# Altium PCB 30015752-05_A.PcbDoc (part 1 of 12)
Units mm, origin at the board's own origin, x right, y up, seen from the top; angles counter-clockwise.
Board outline 100.05 x 72 mm, 10 copper layers (Top, GND_2, Signal_3, Signal_4, PWR_5, GND_6, Signal_7, Signal_8, GND_9, Bottom), stack 1.493 mm thick; 577 components, 546 nets, 2389 pads, 1412 vias.
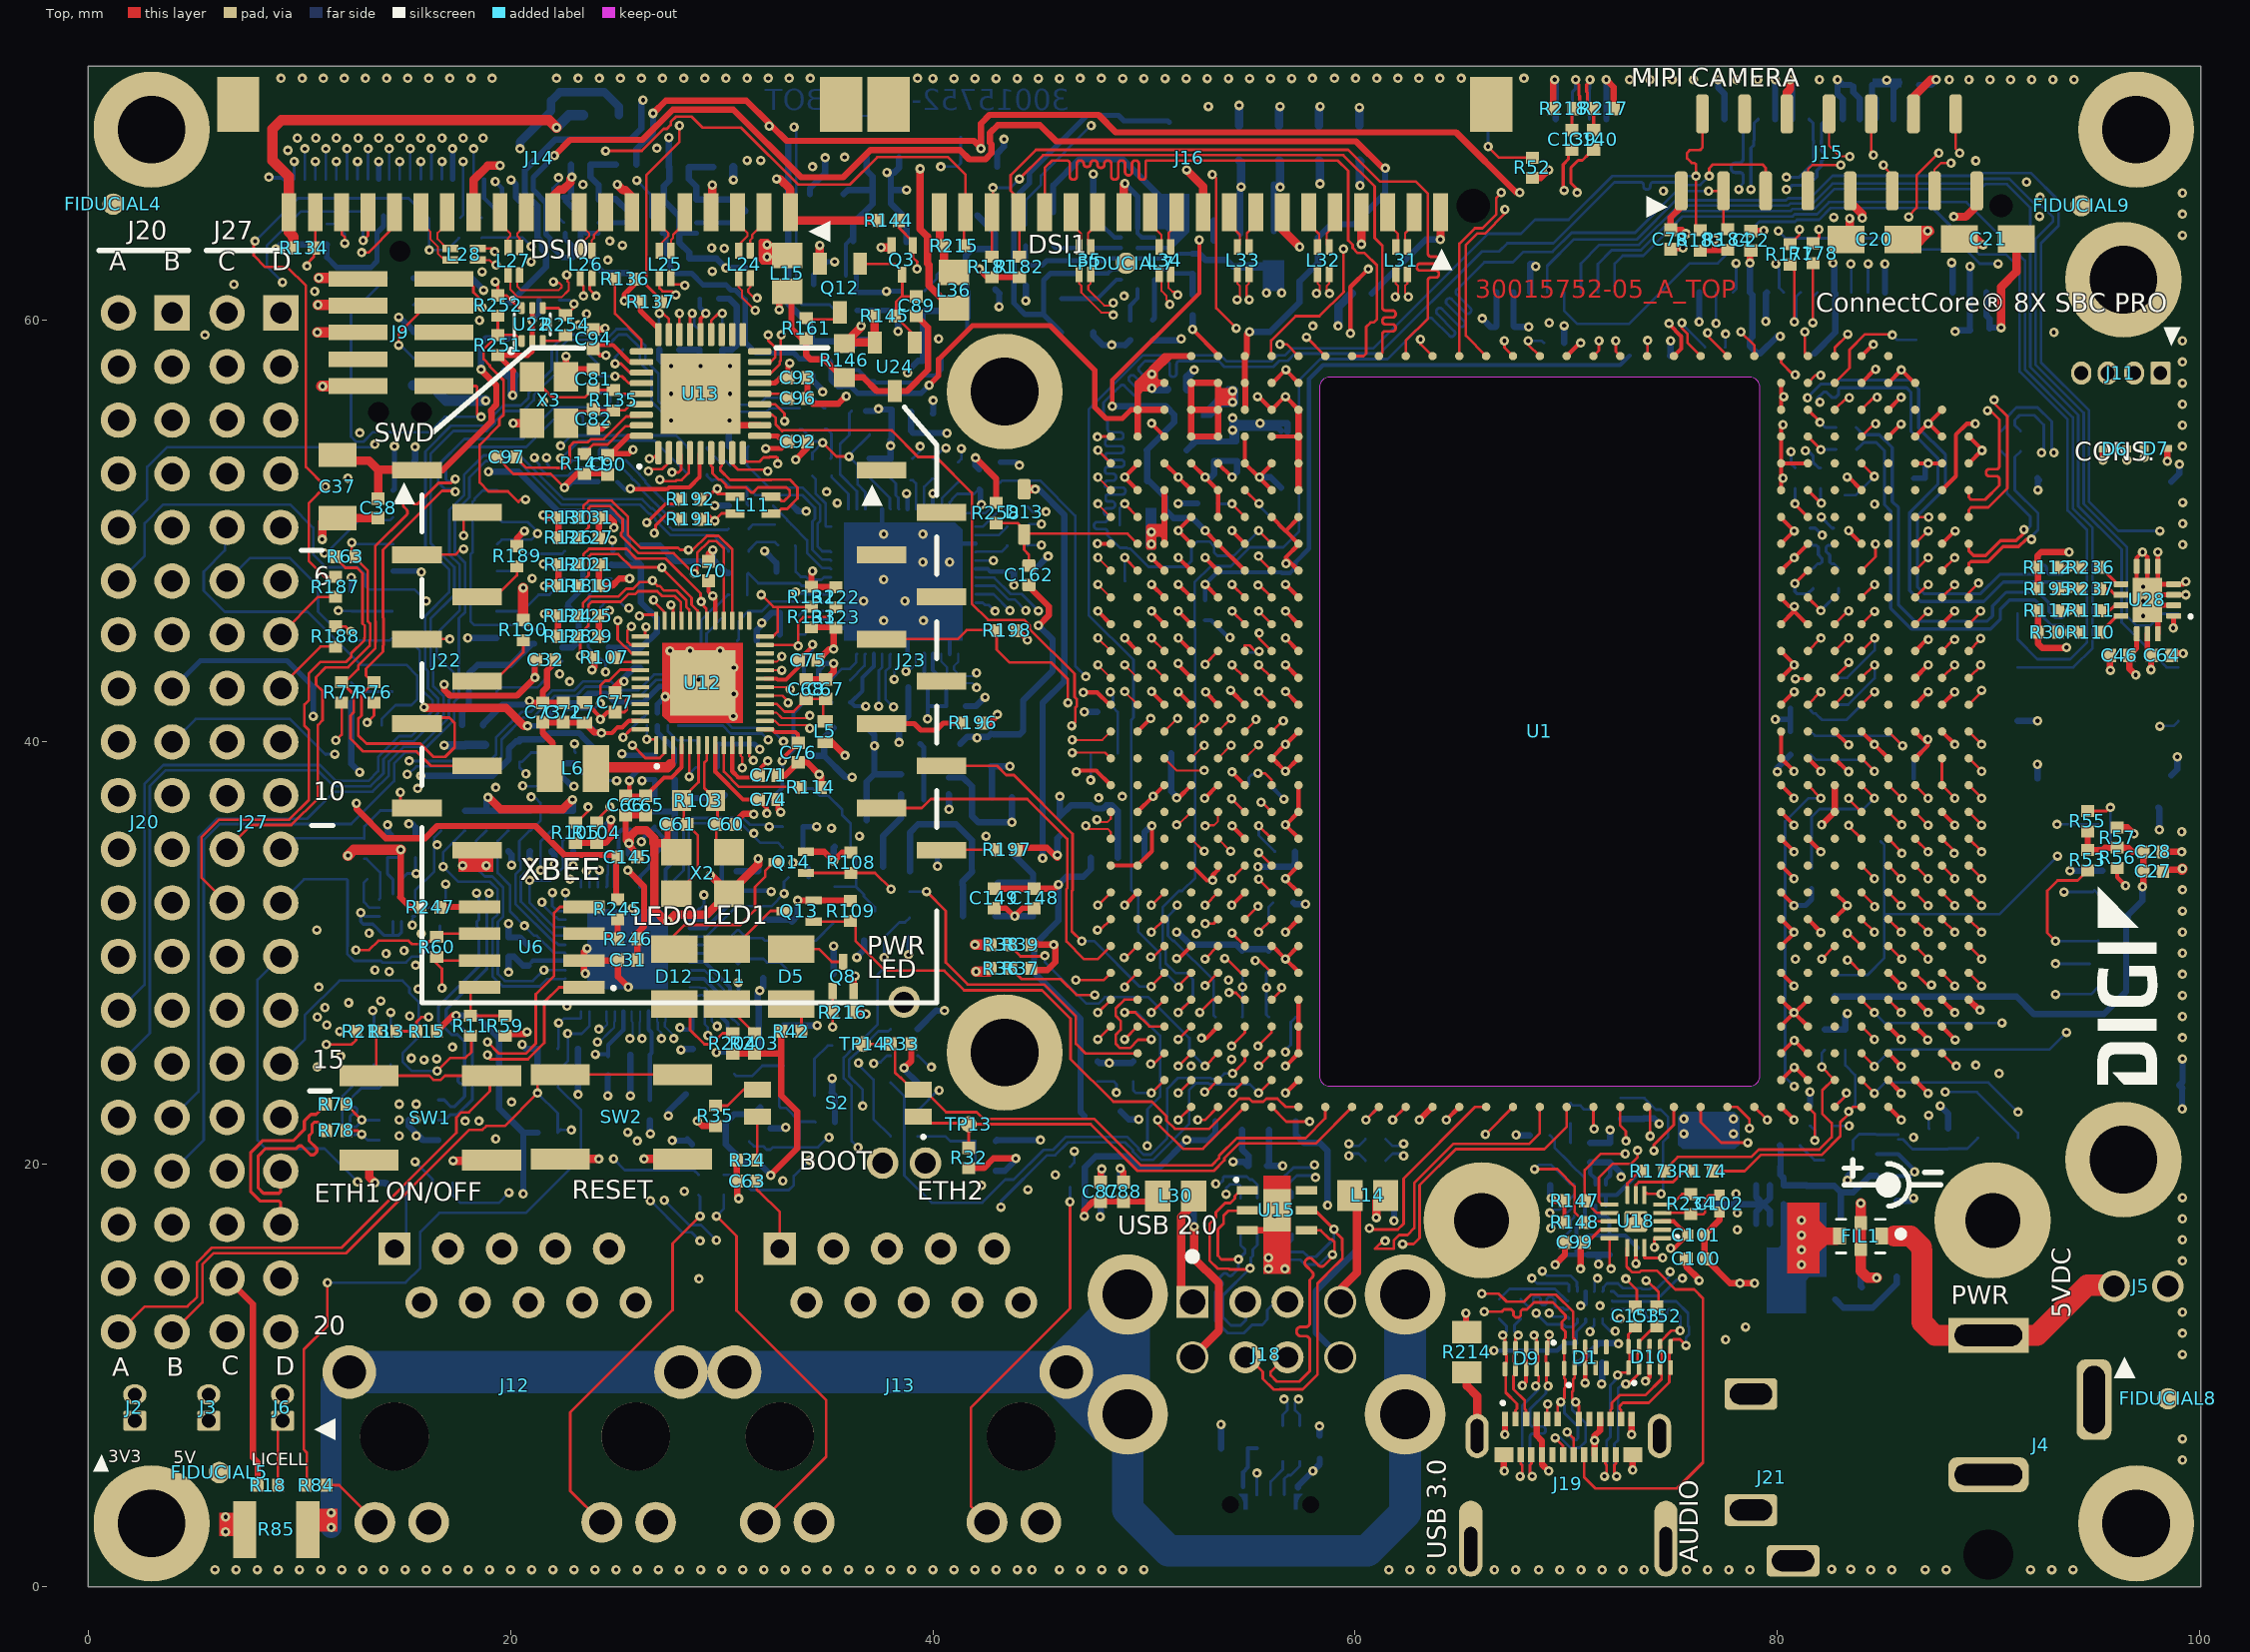
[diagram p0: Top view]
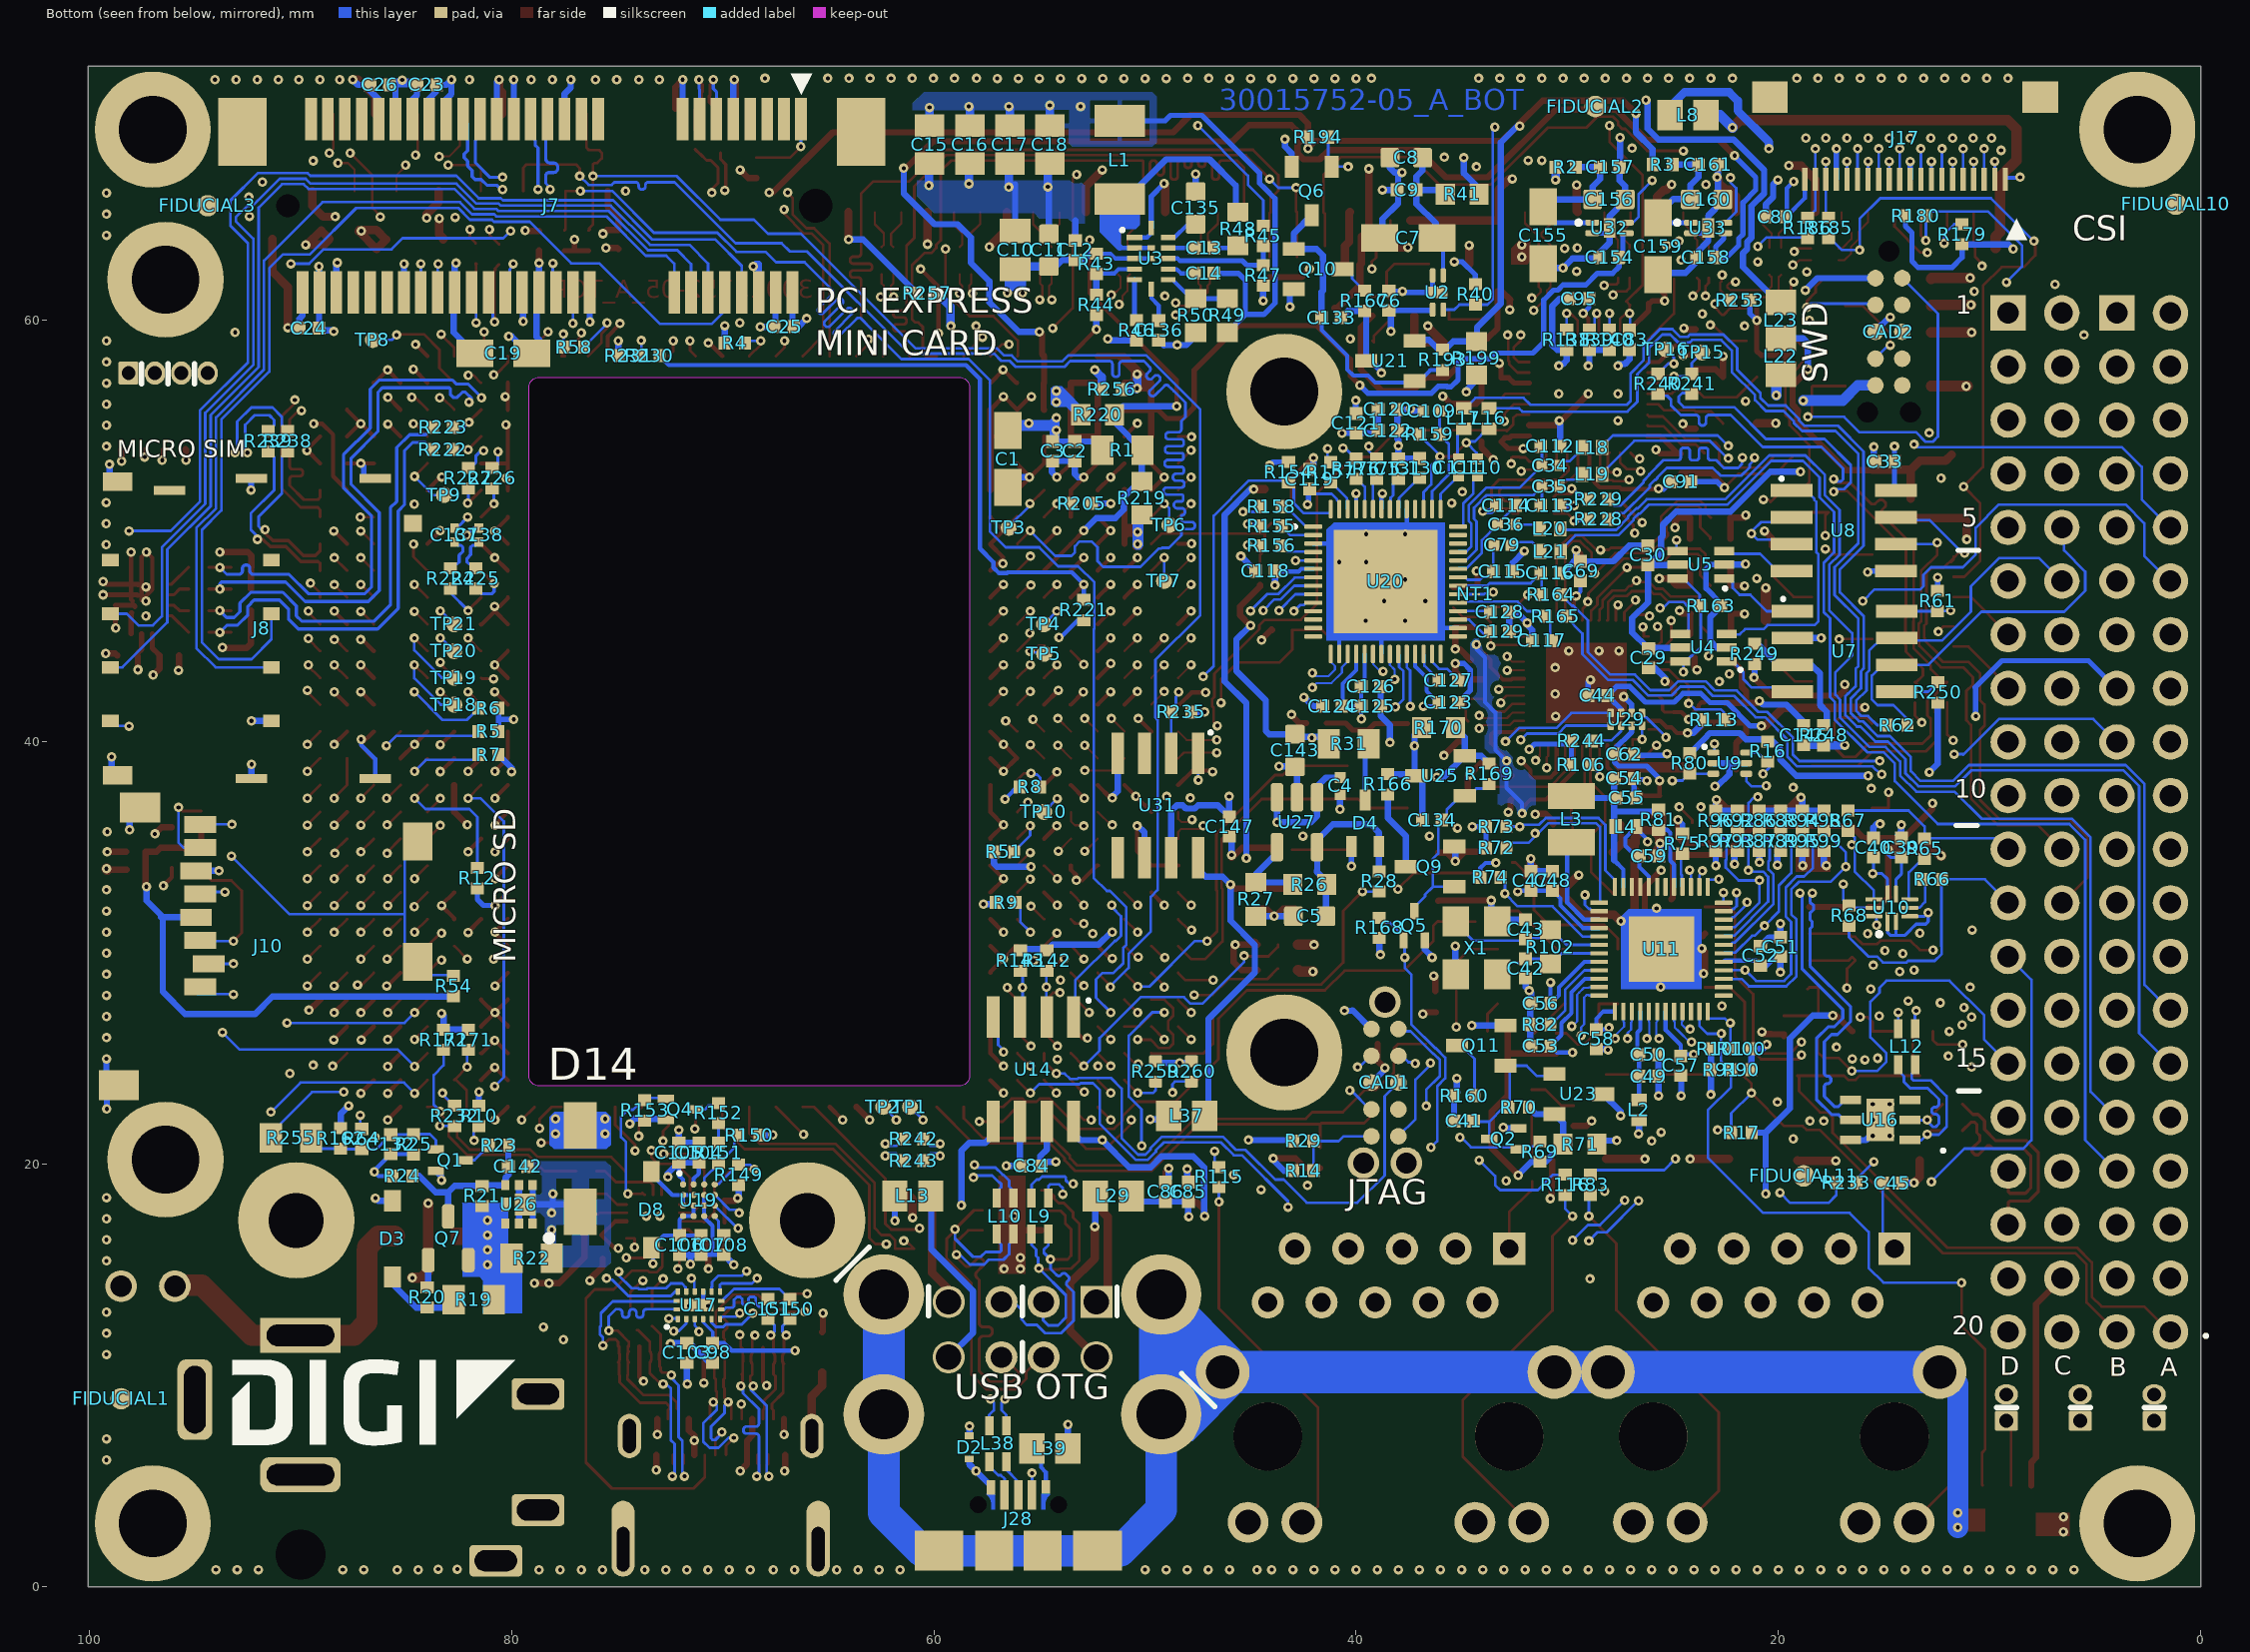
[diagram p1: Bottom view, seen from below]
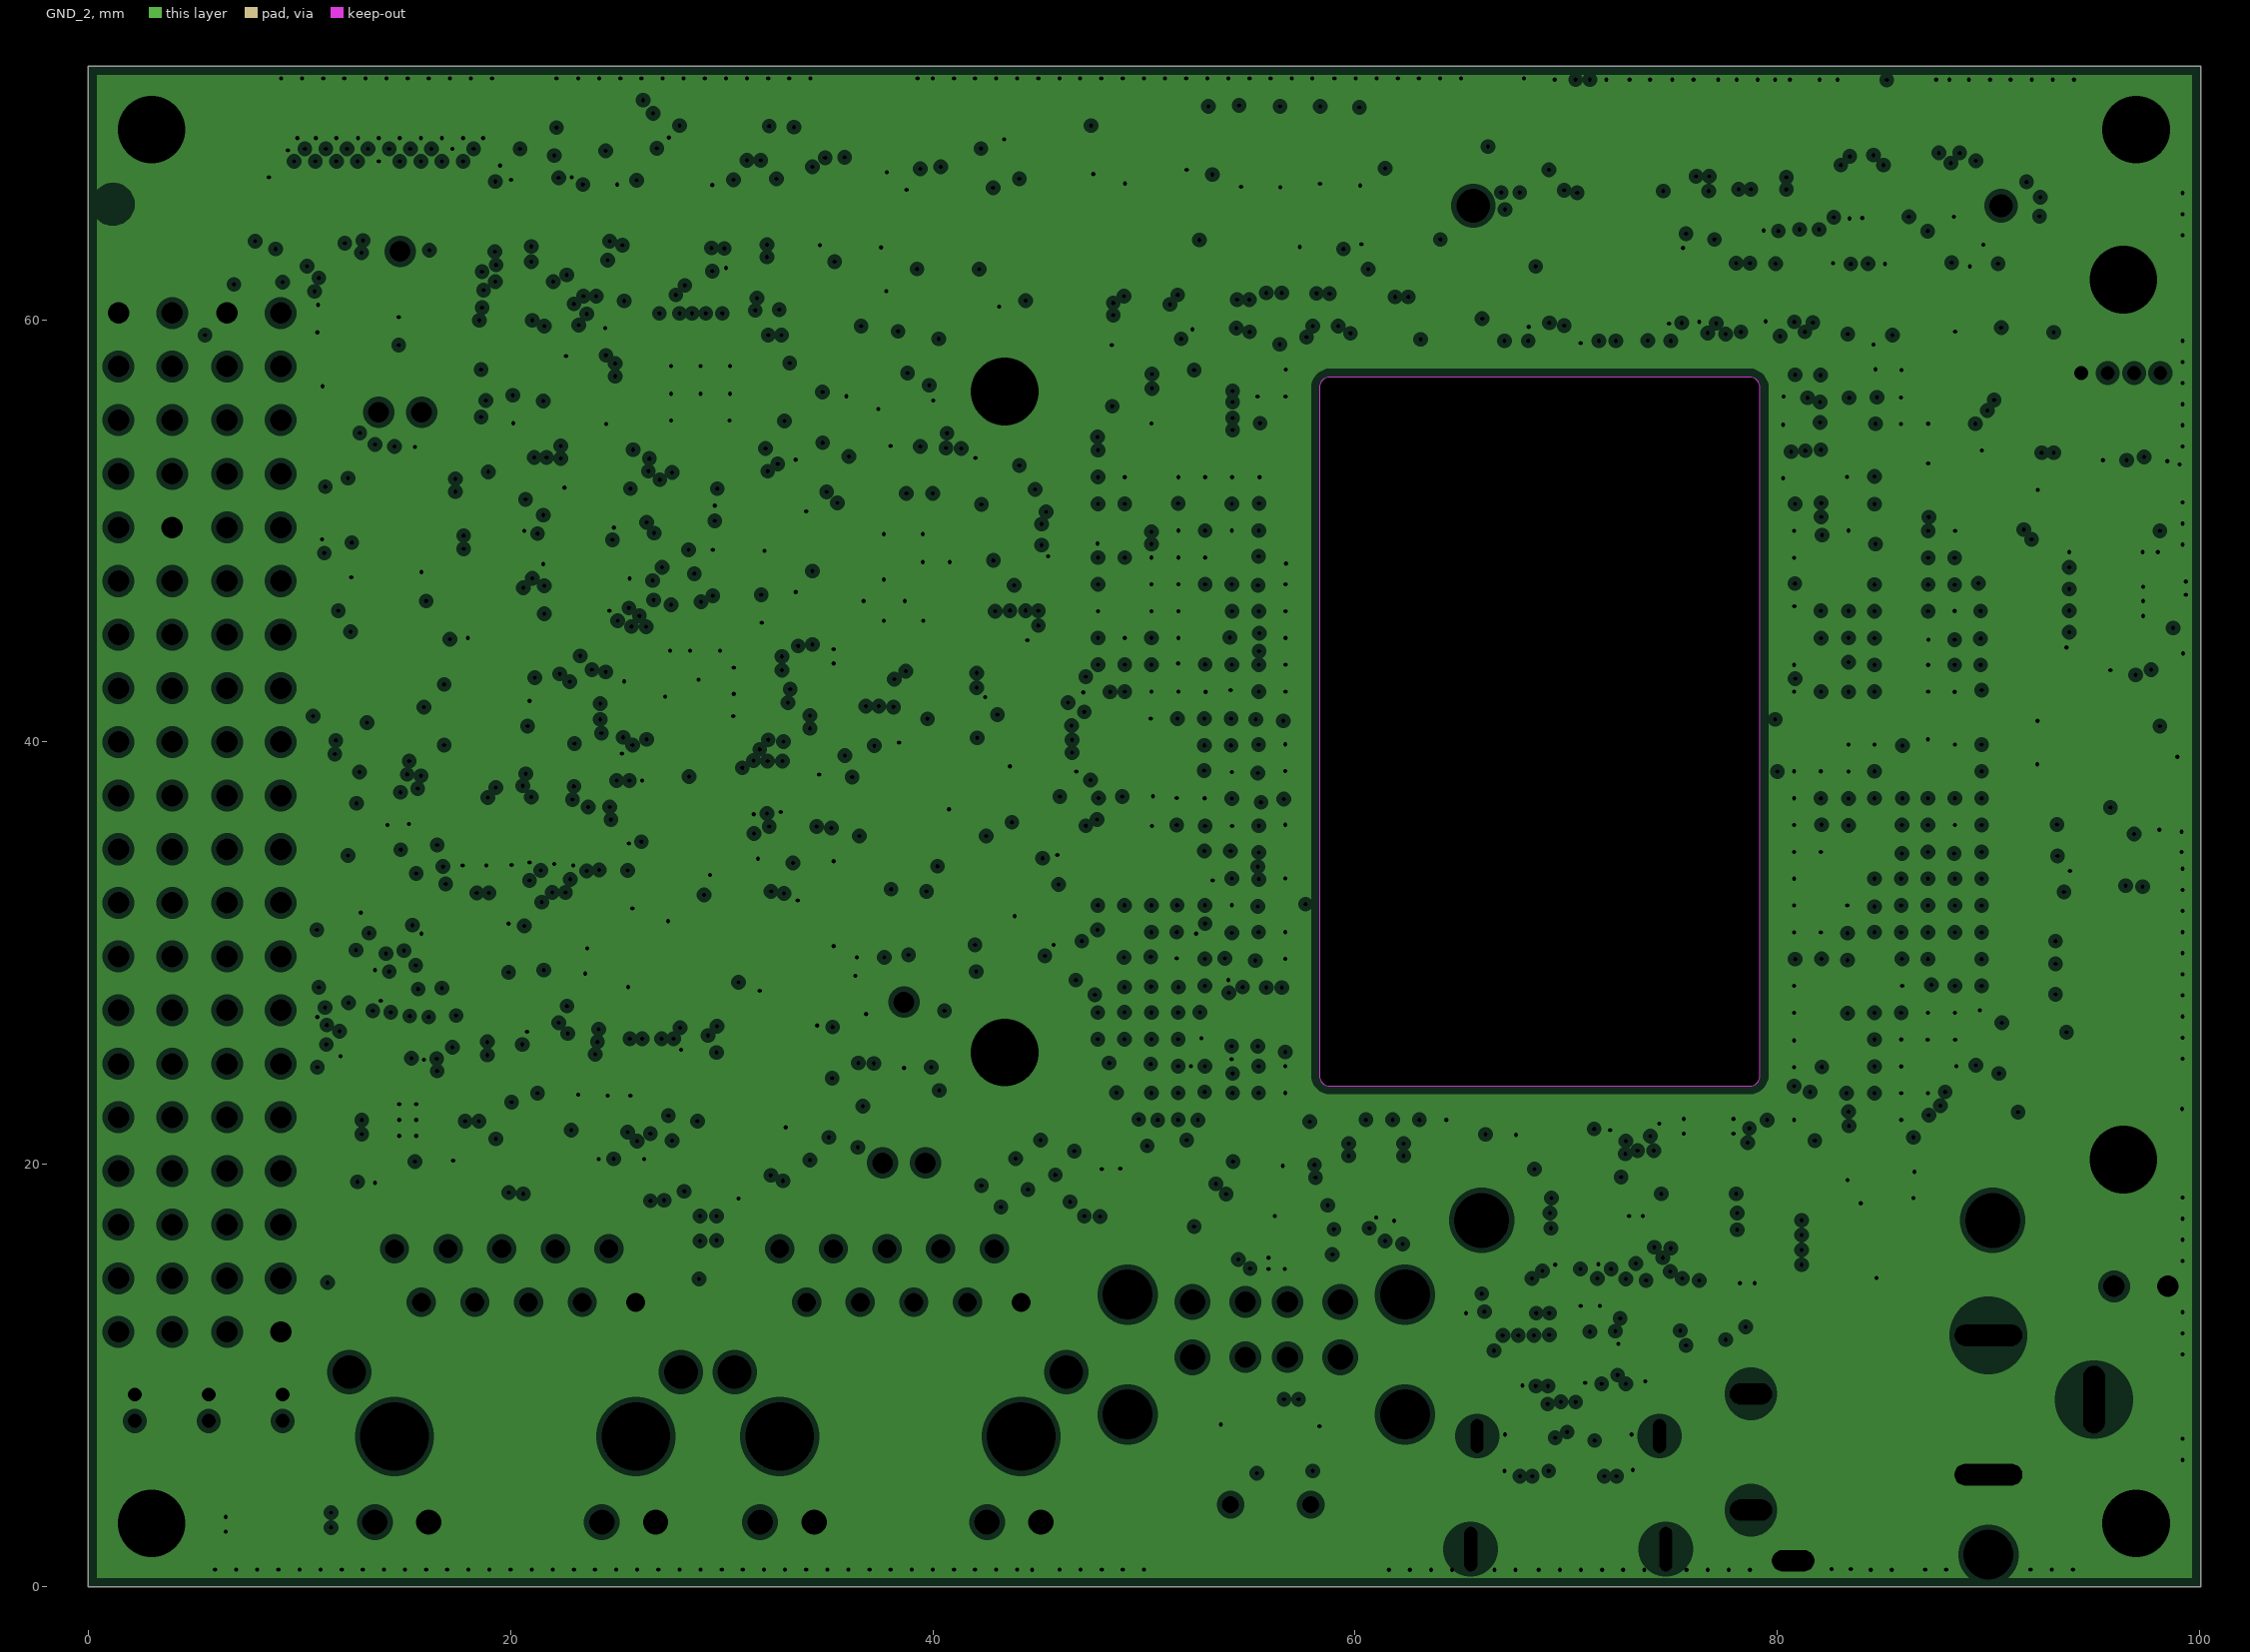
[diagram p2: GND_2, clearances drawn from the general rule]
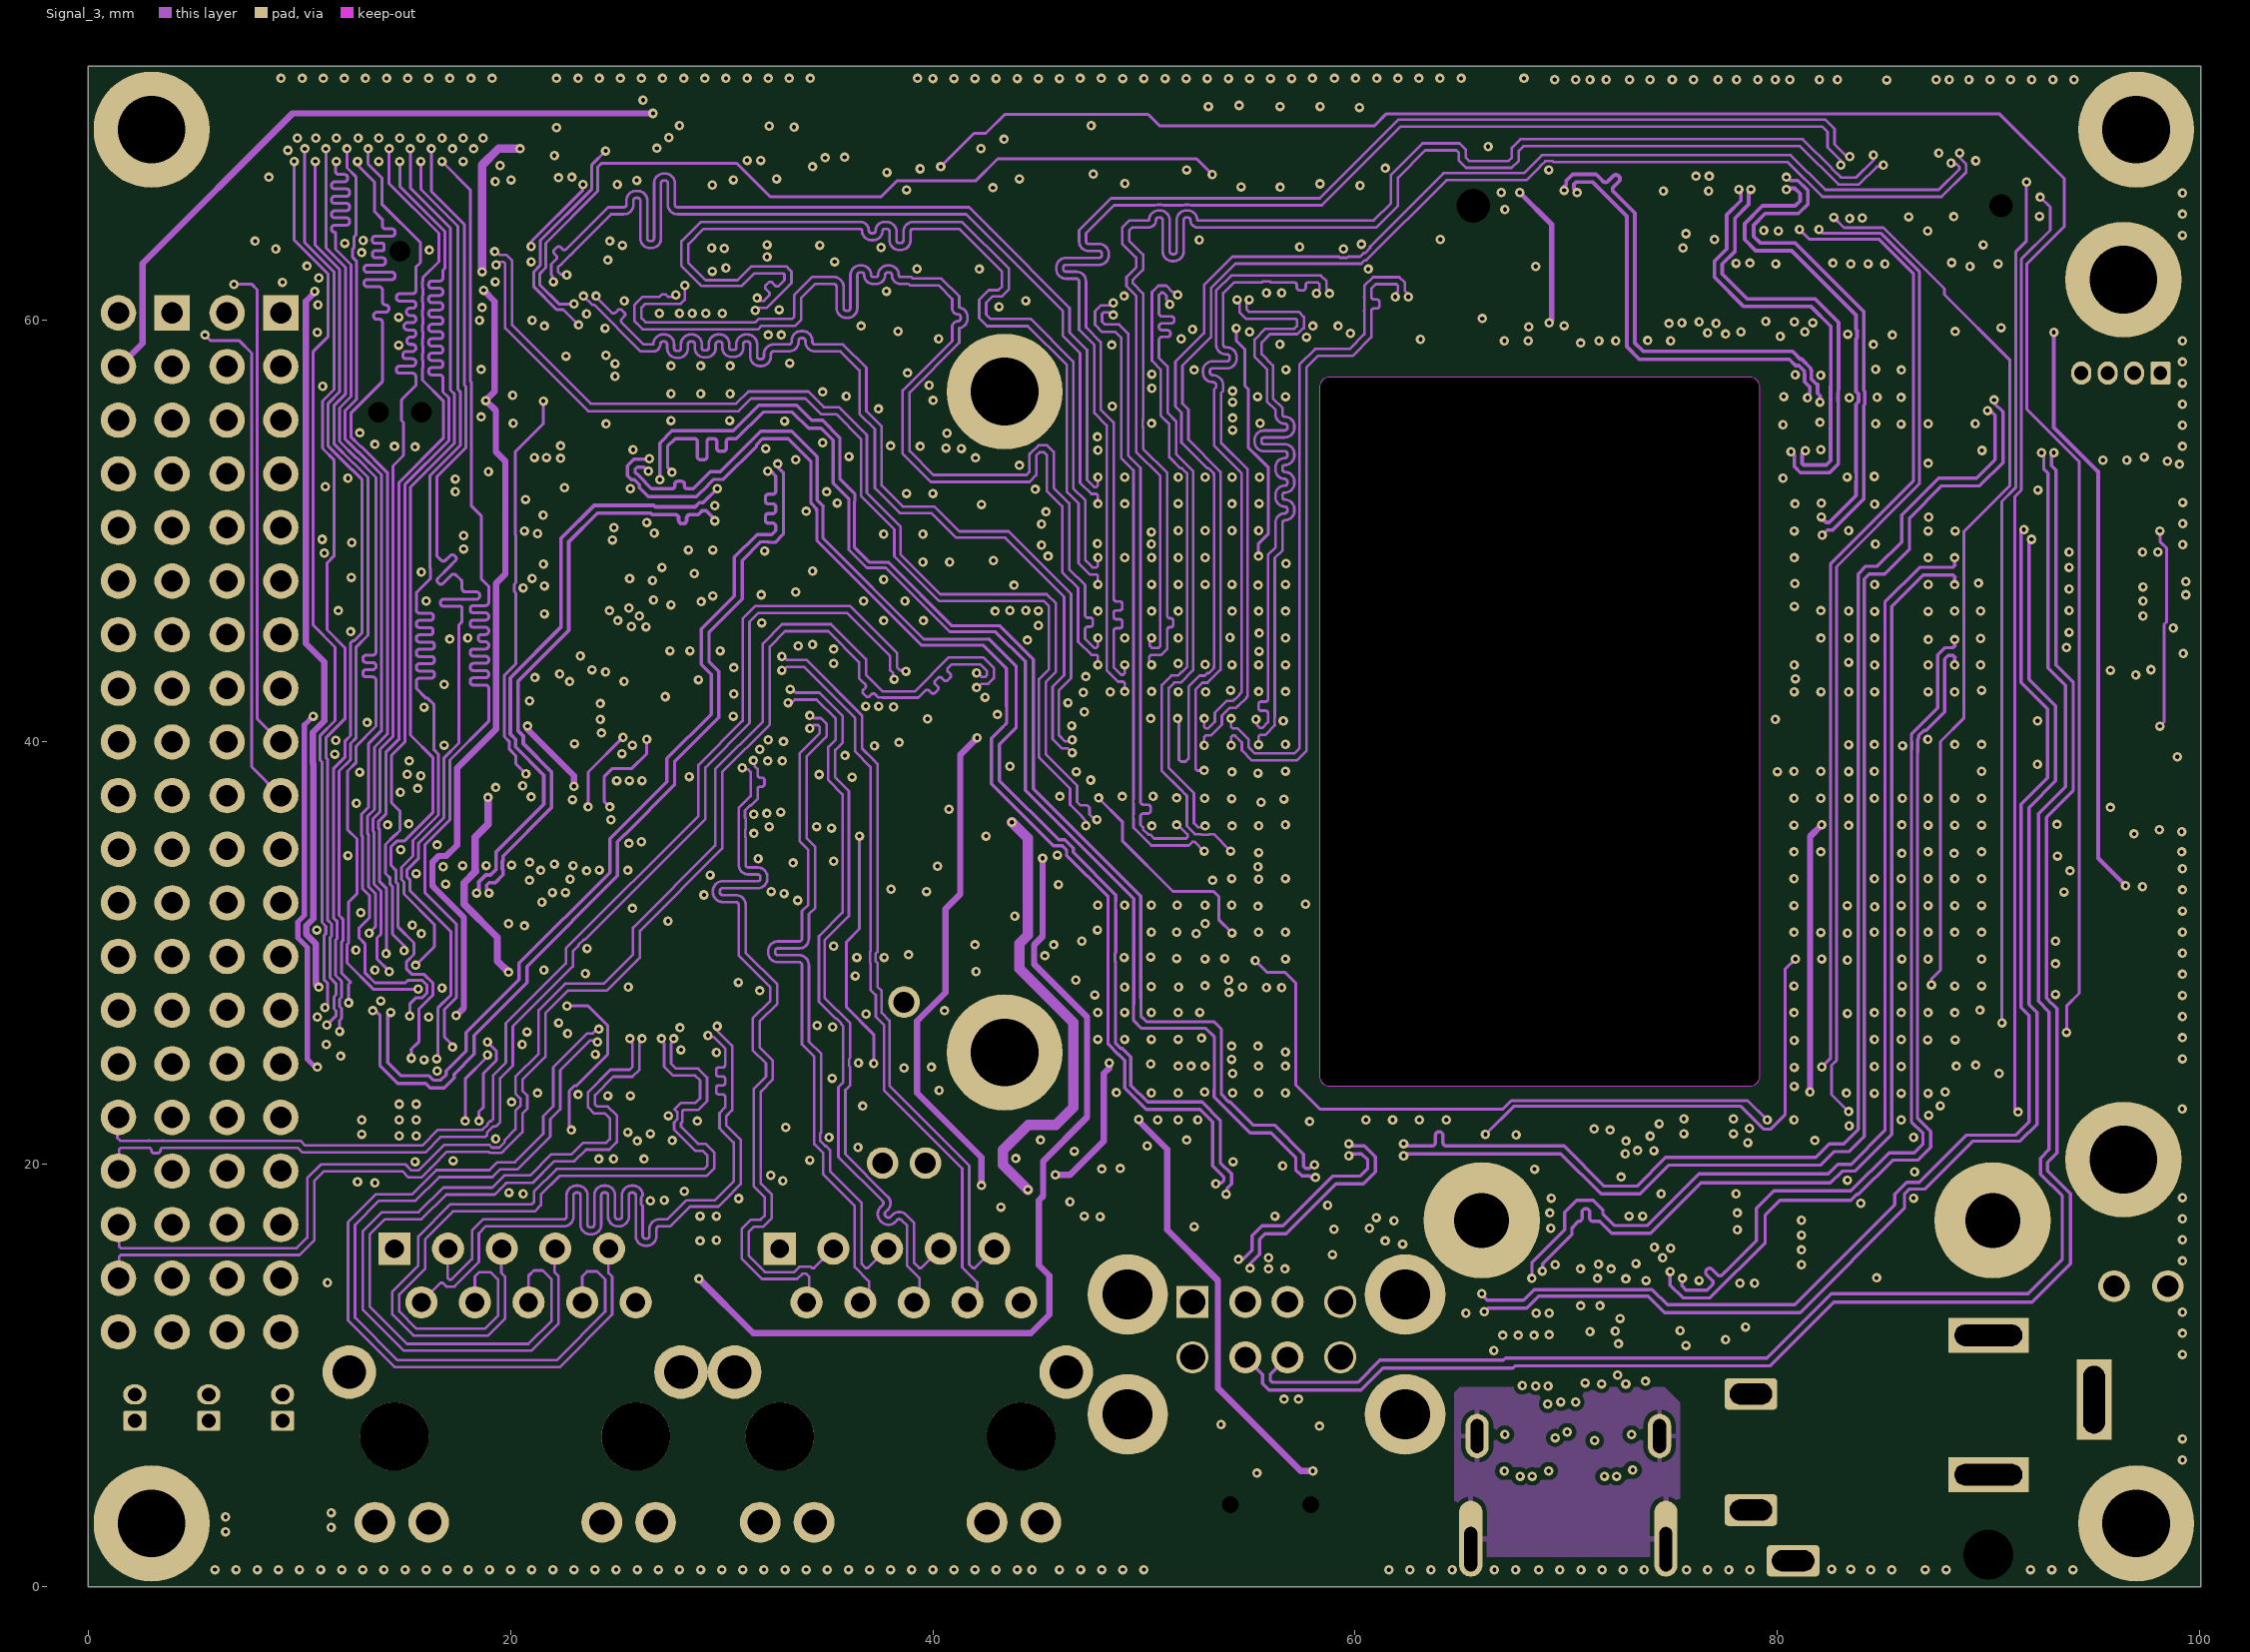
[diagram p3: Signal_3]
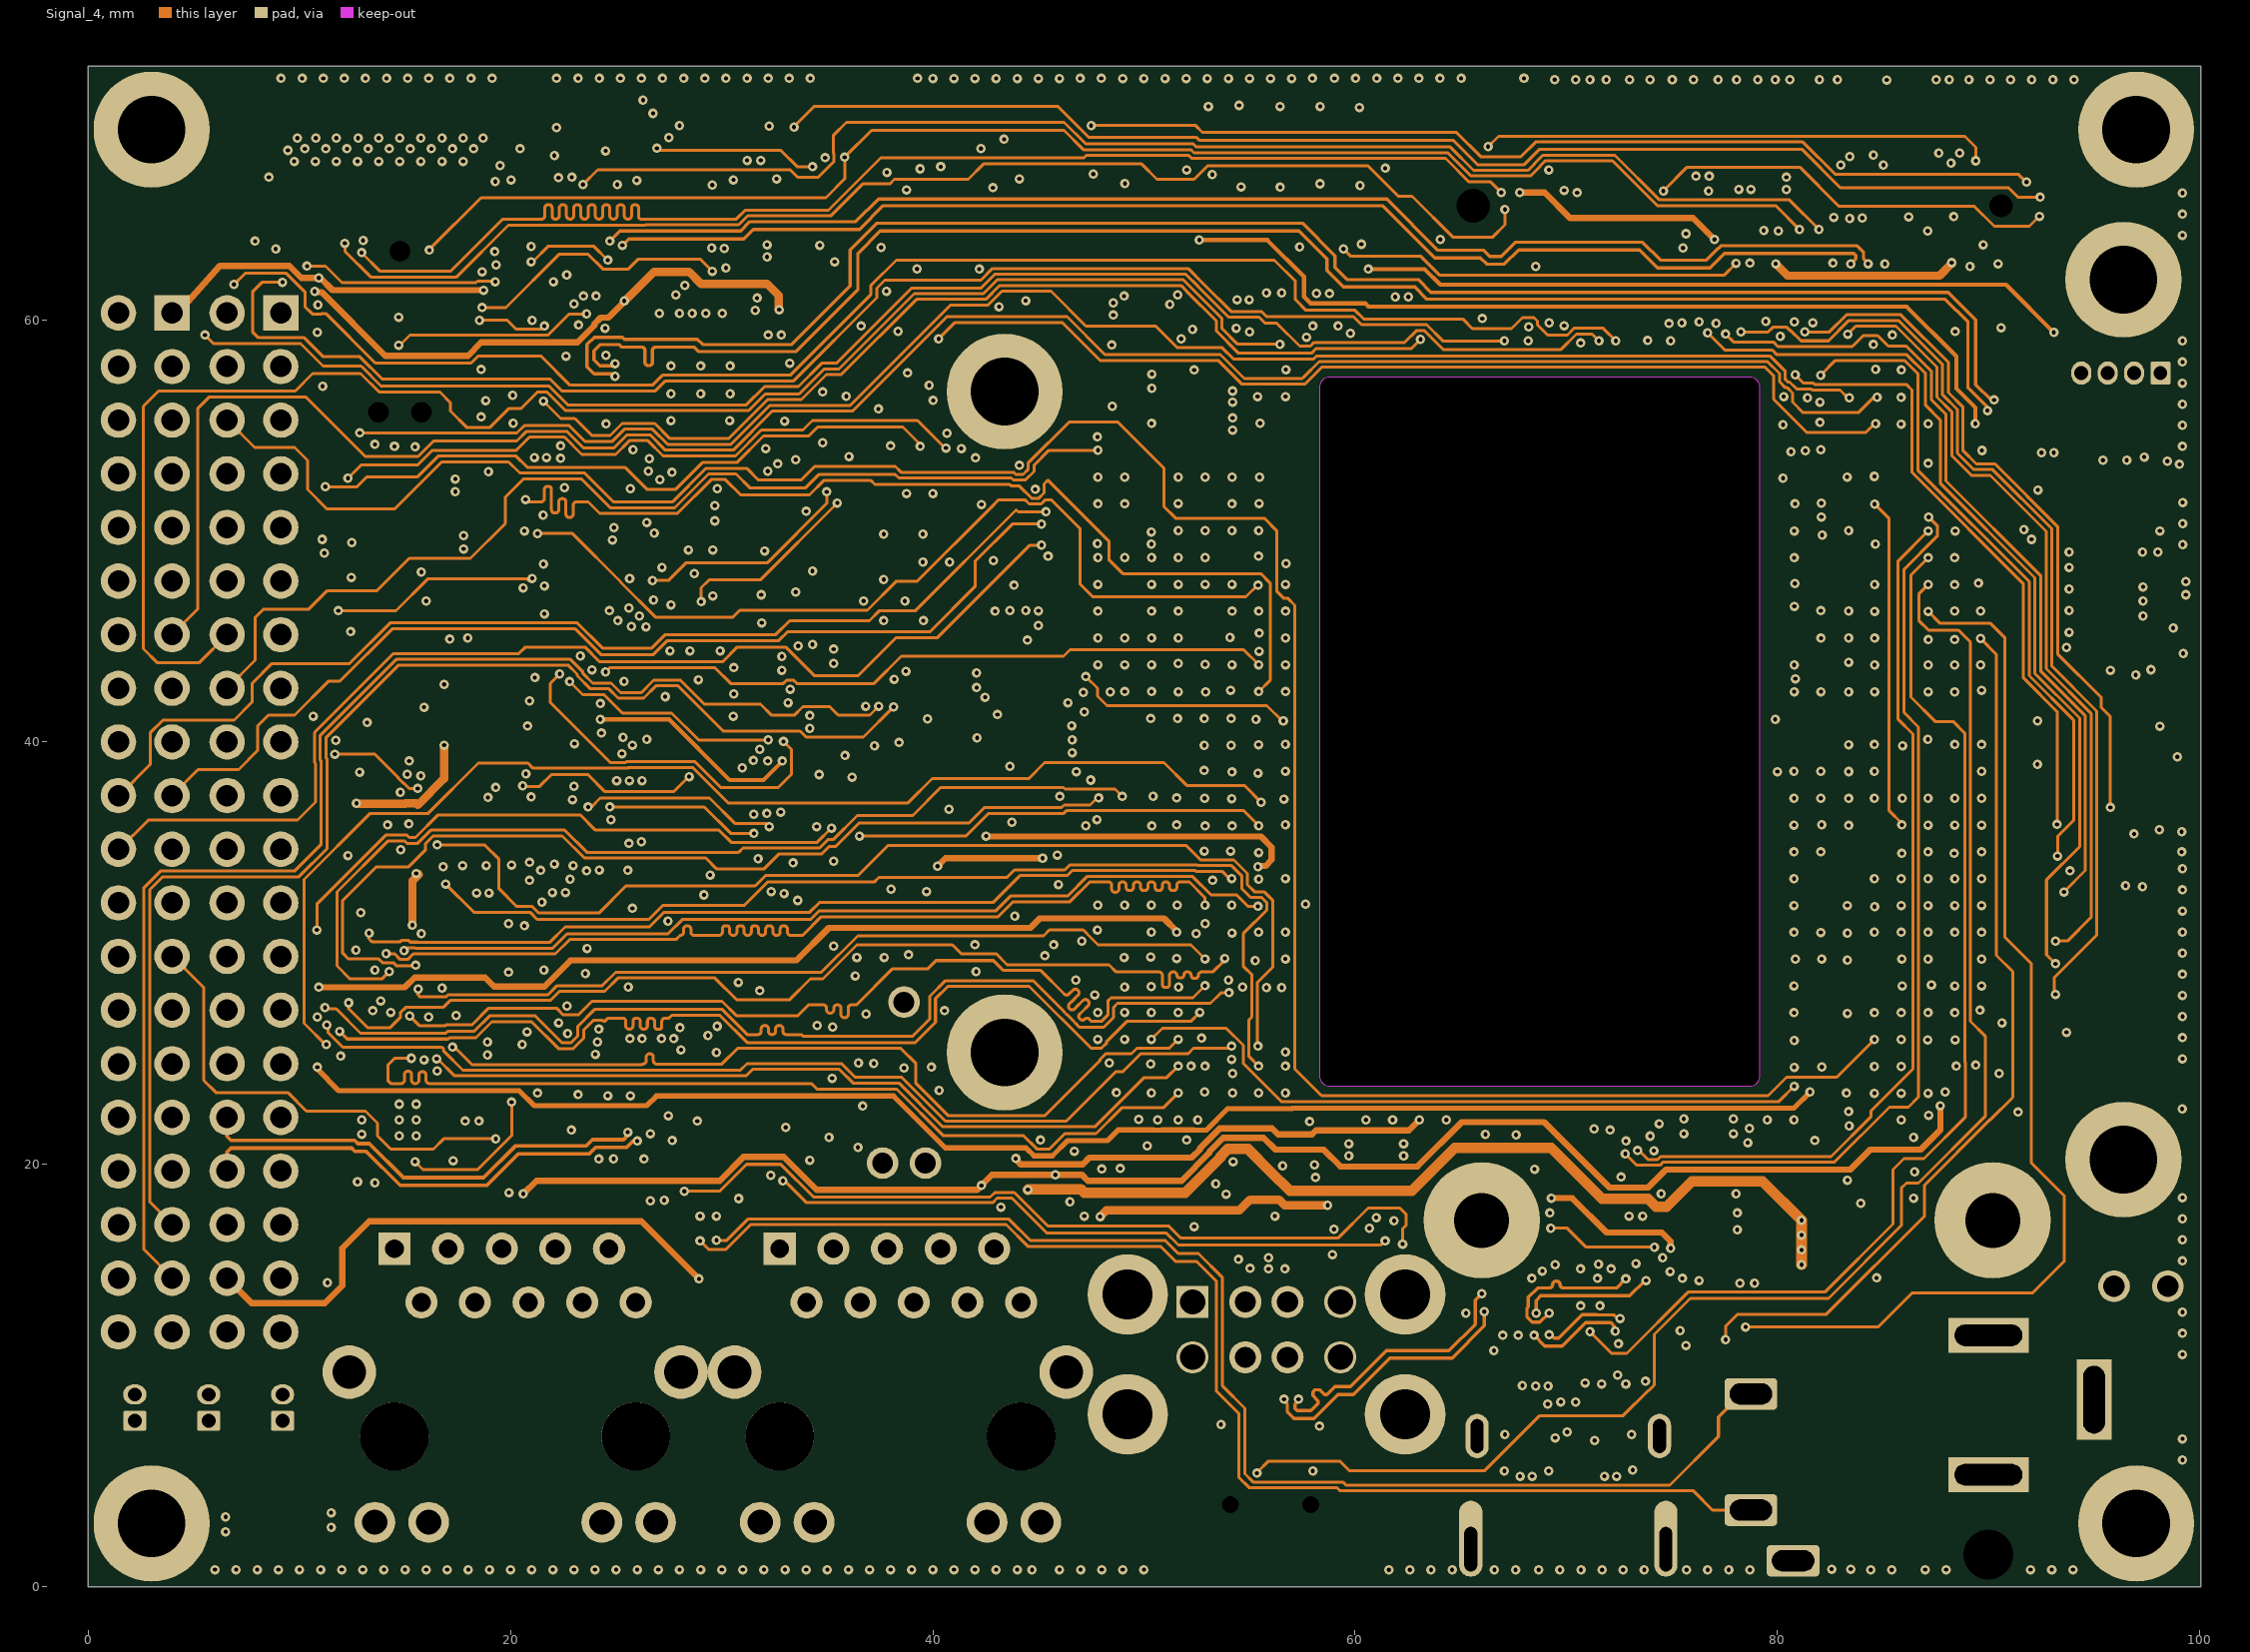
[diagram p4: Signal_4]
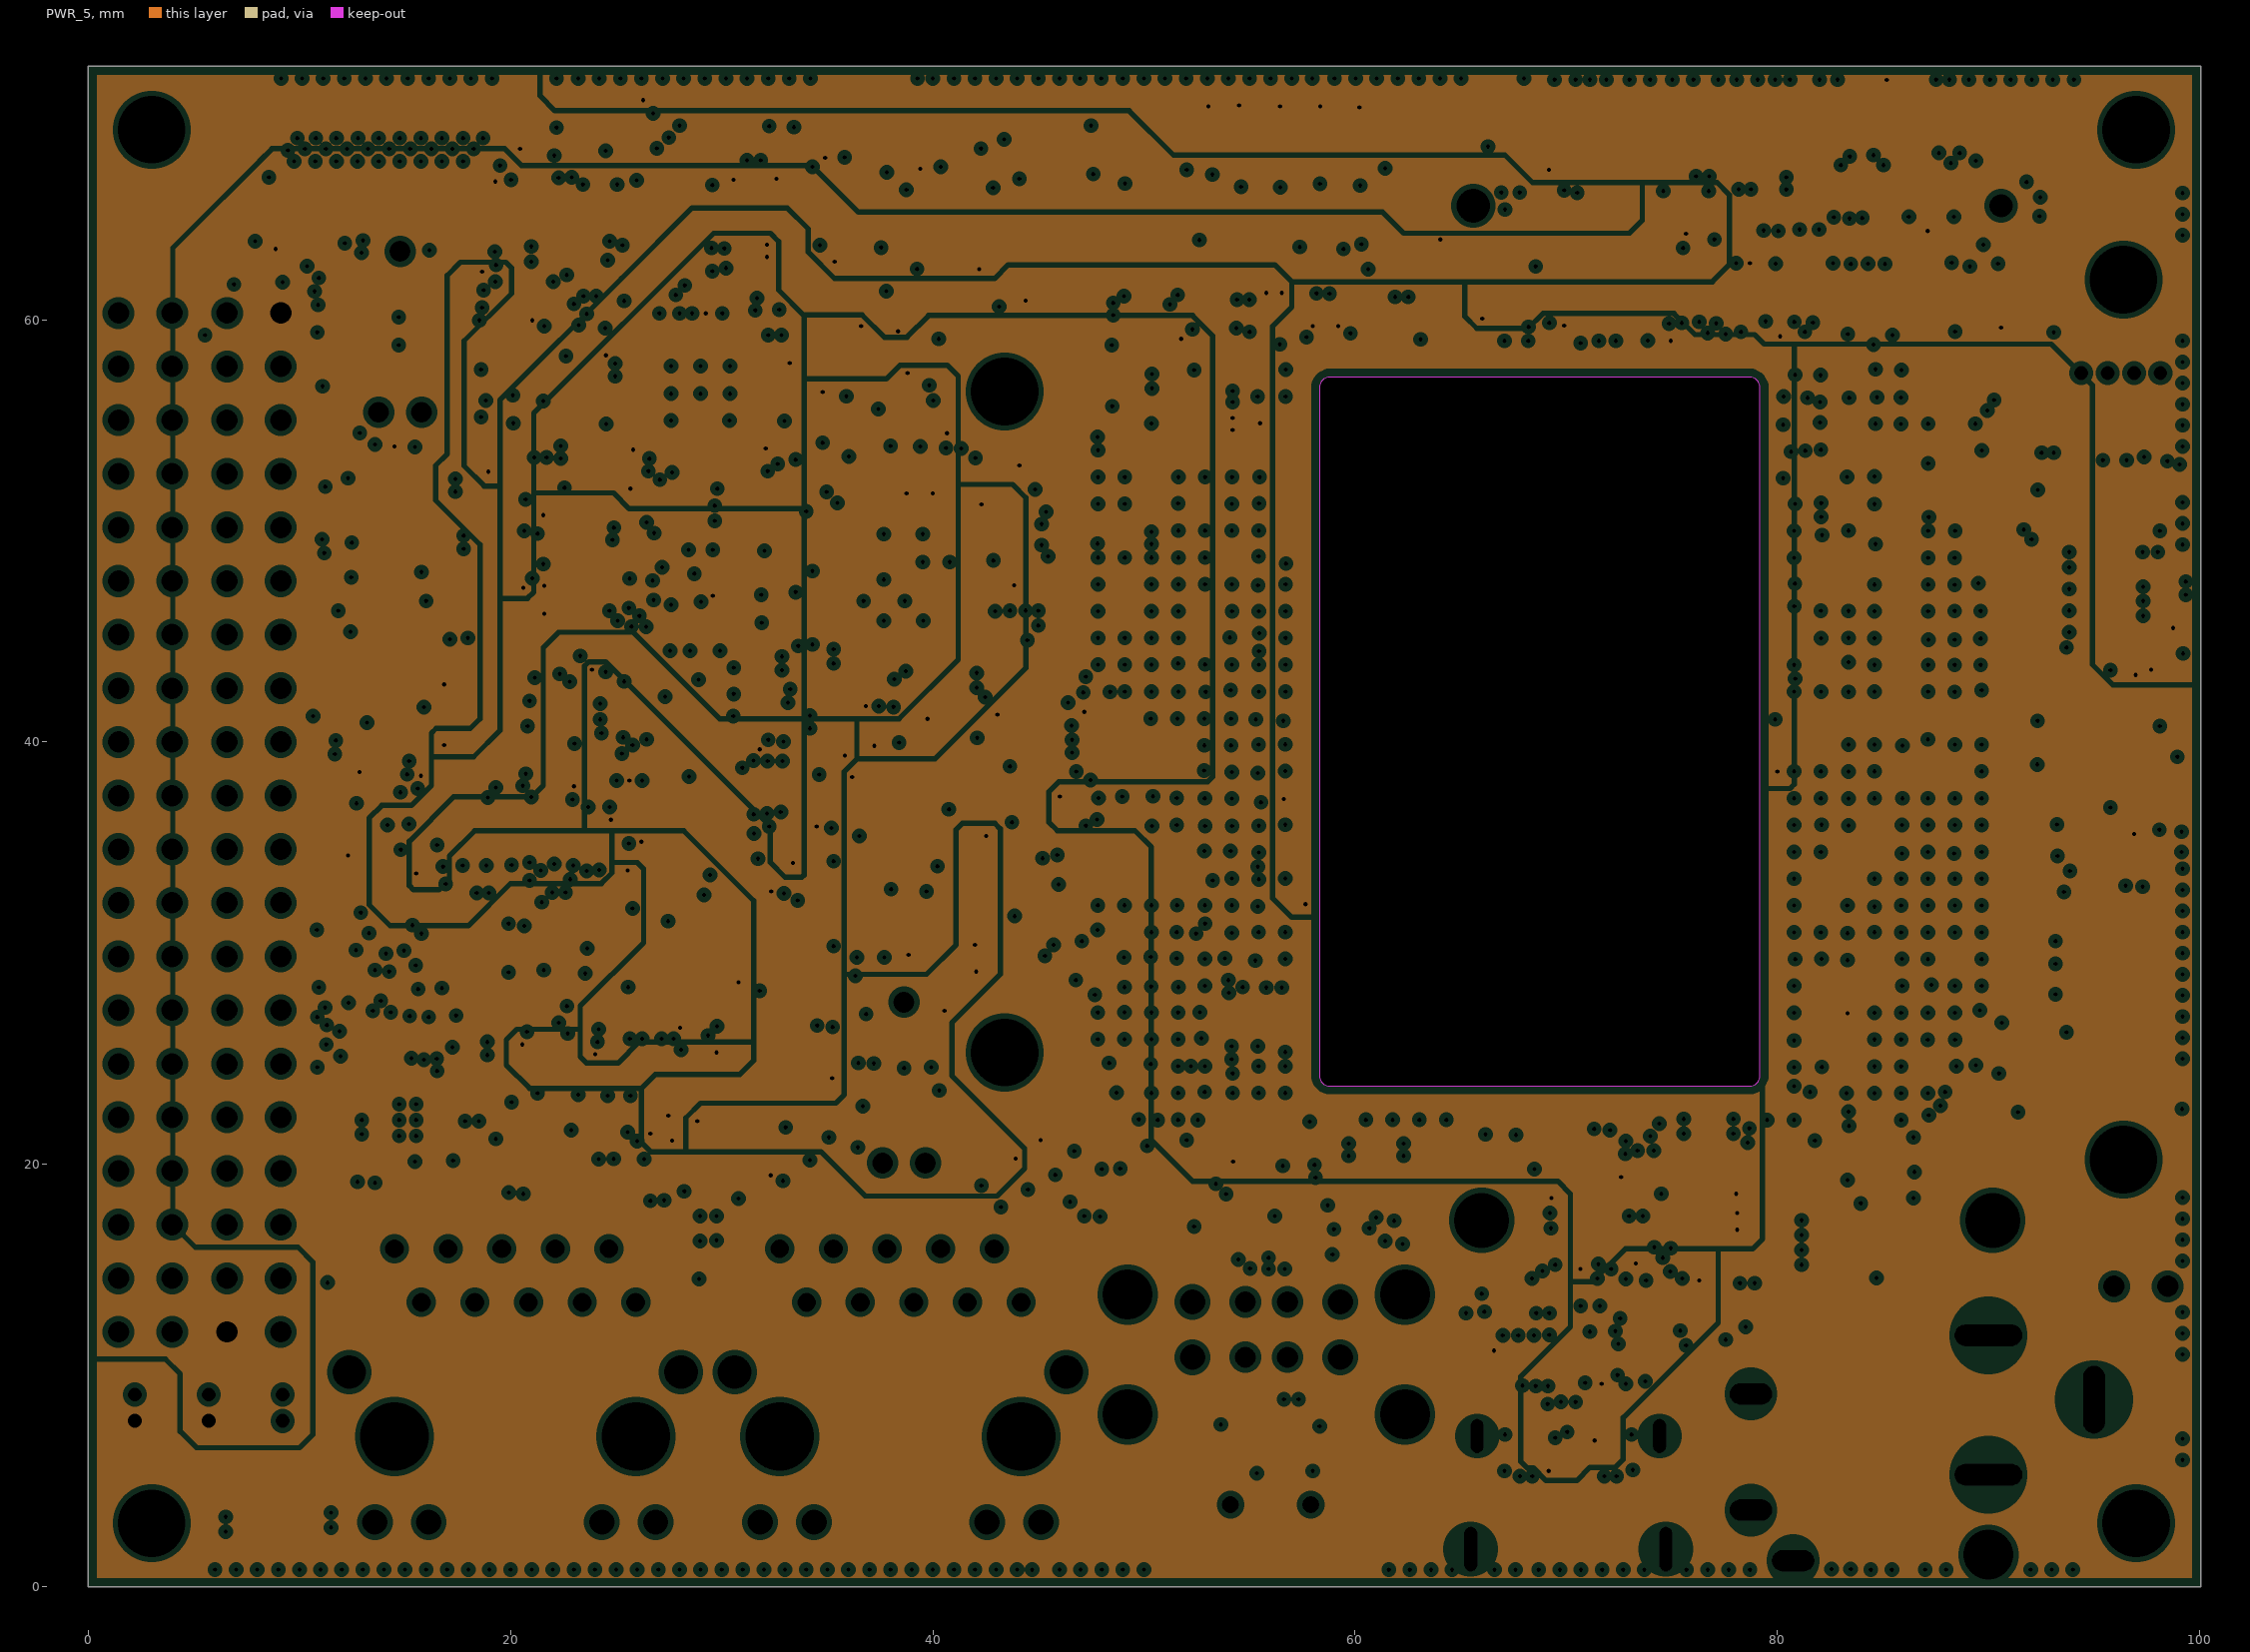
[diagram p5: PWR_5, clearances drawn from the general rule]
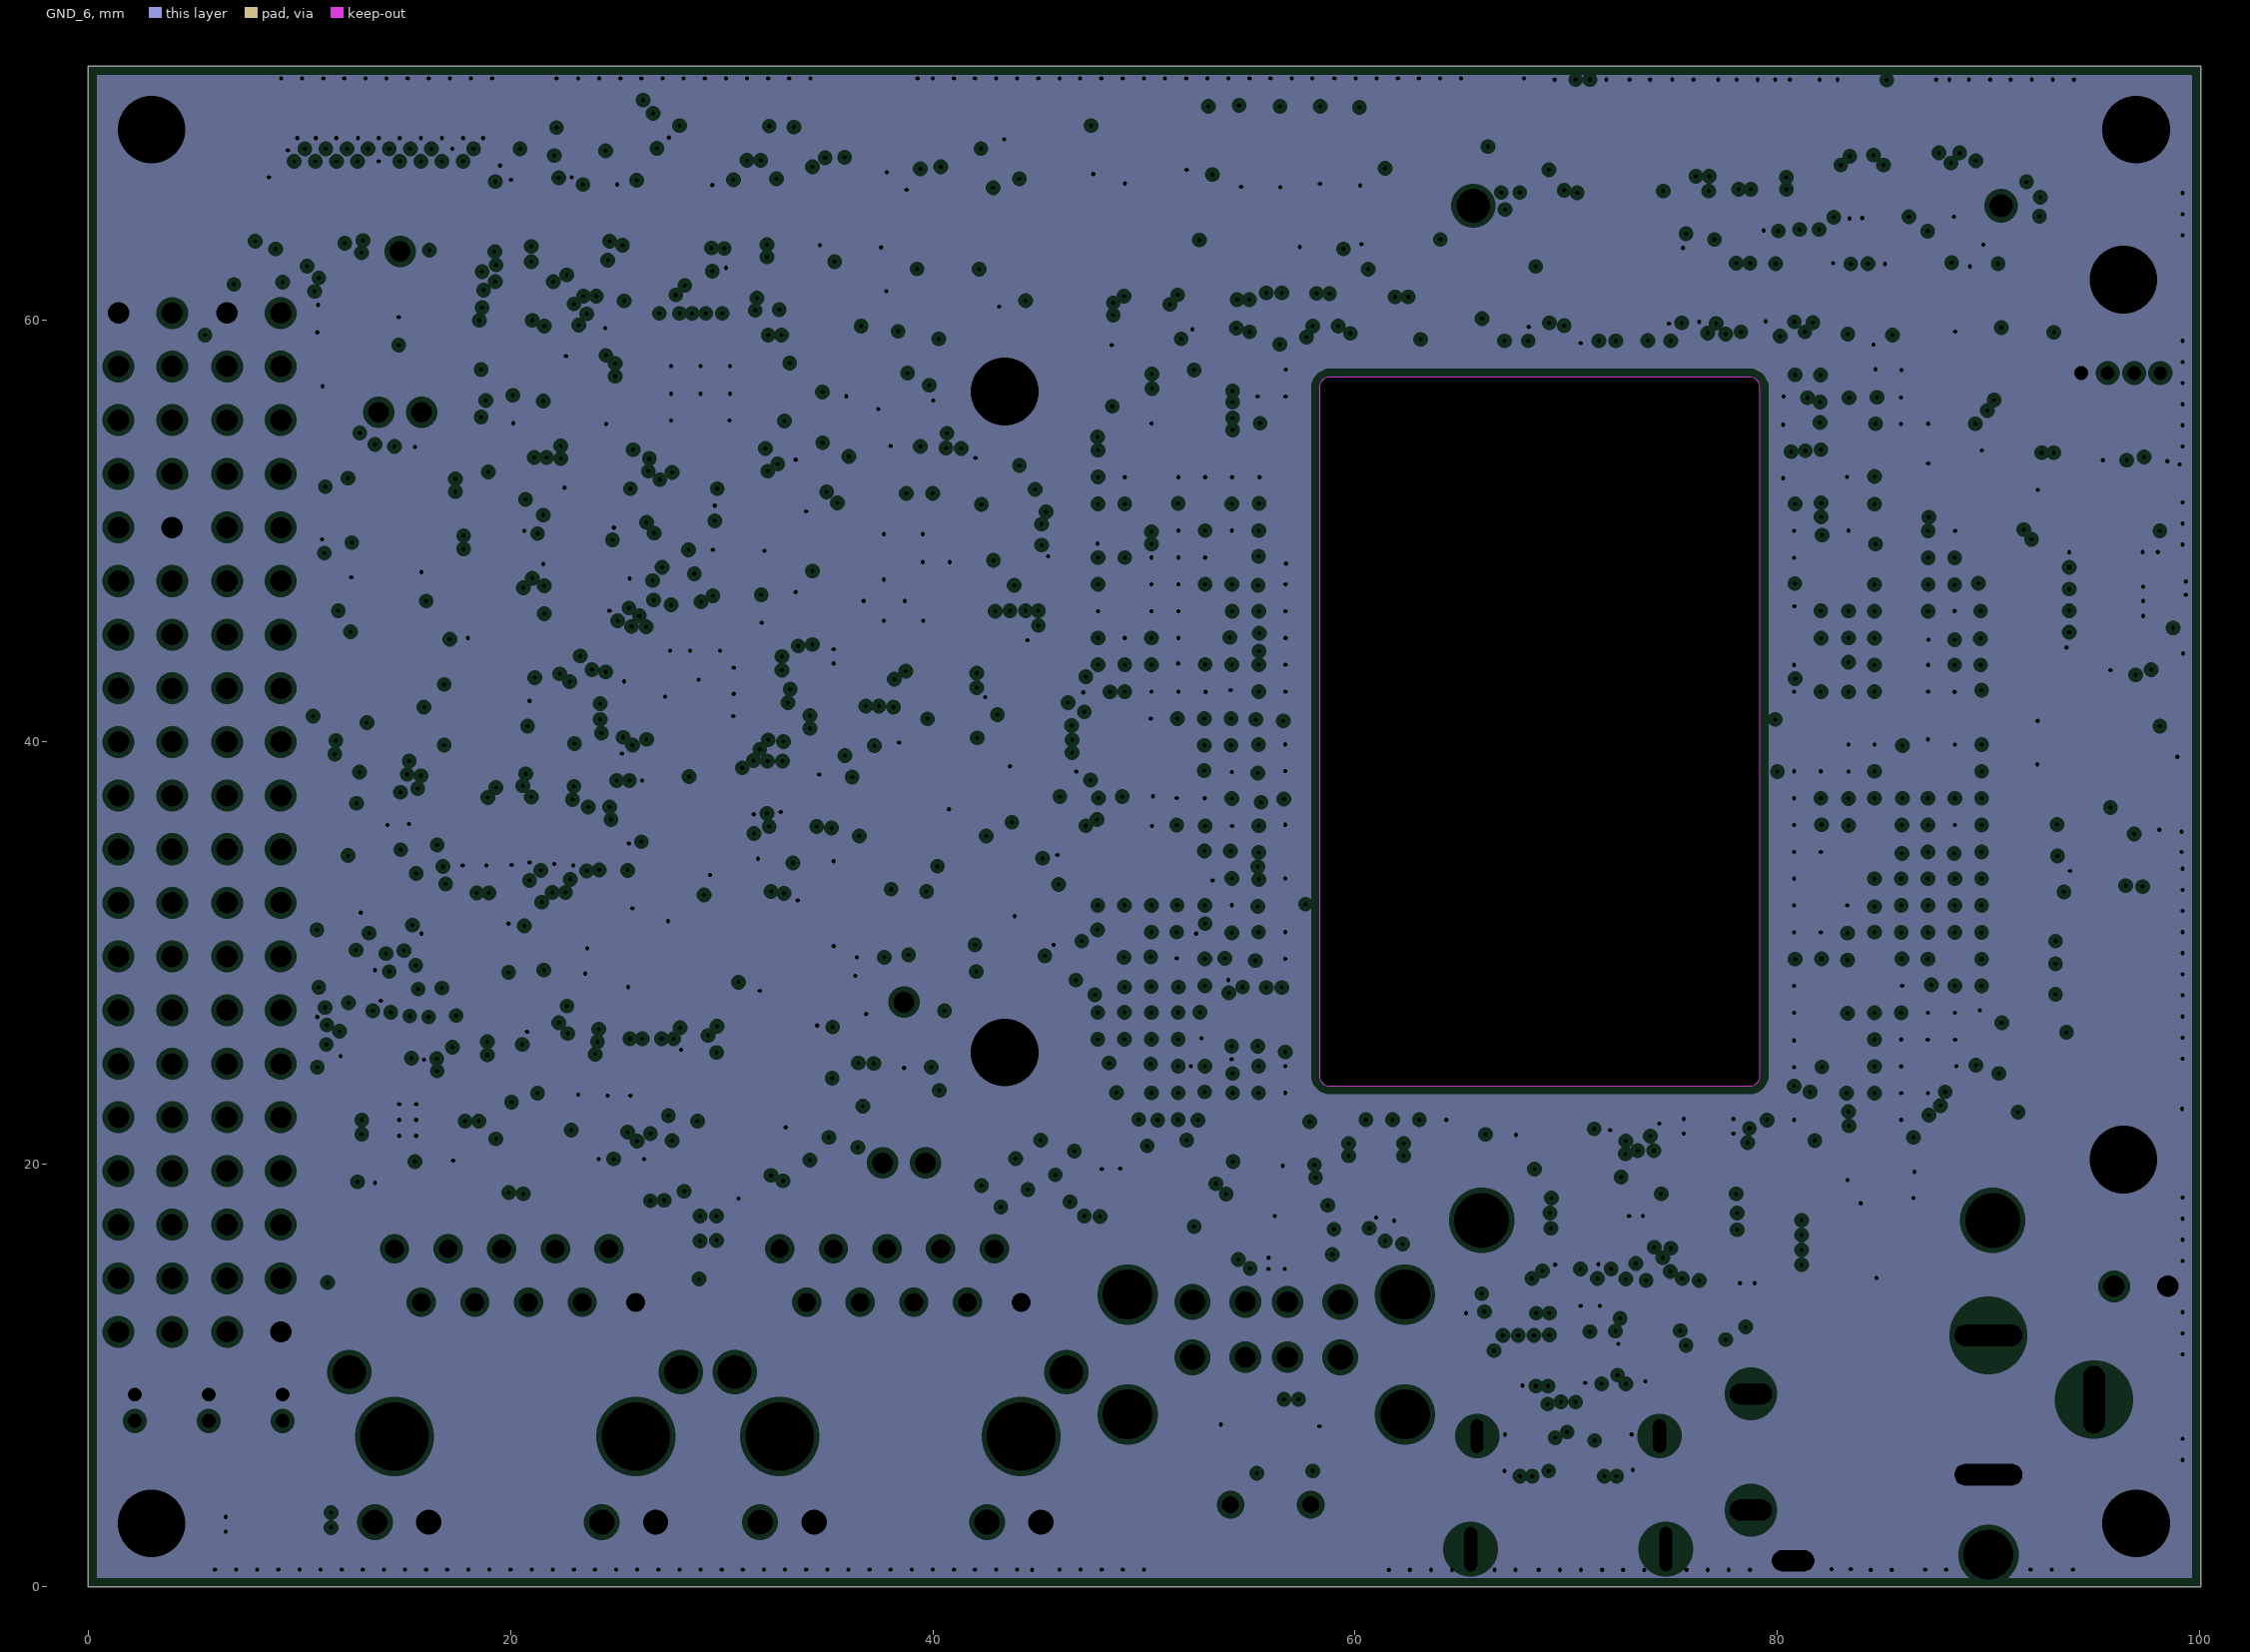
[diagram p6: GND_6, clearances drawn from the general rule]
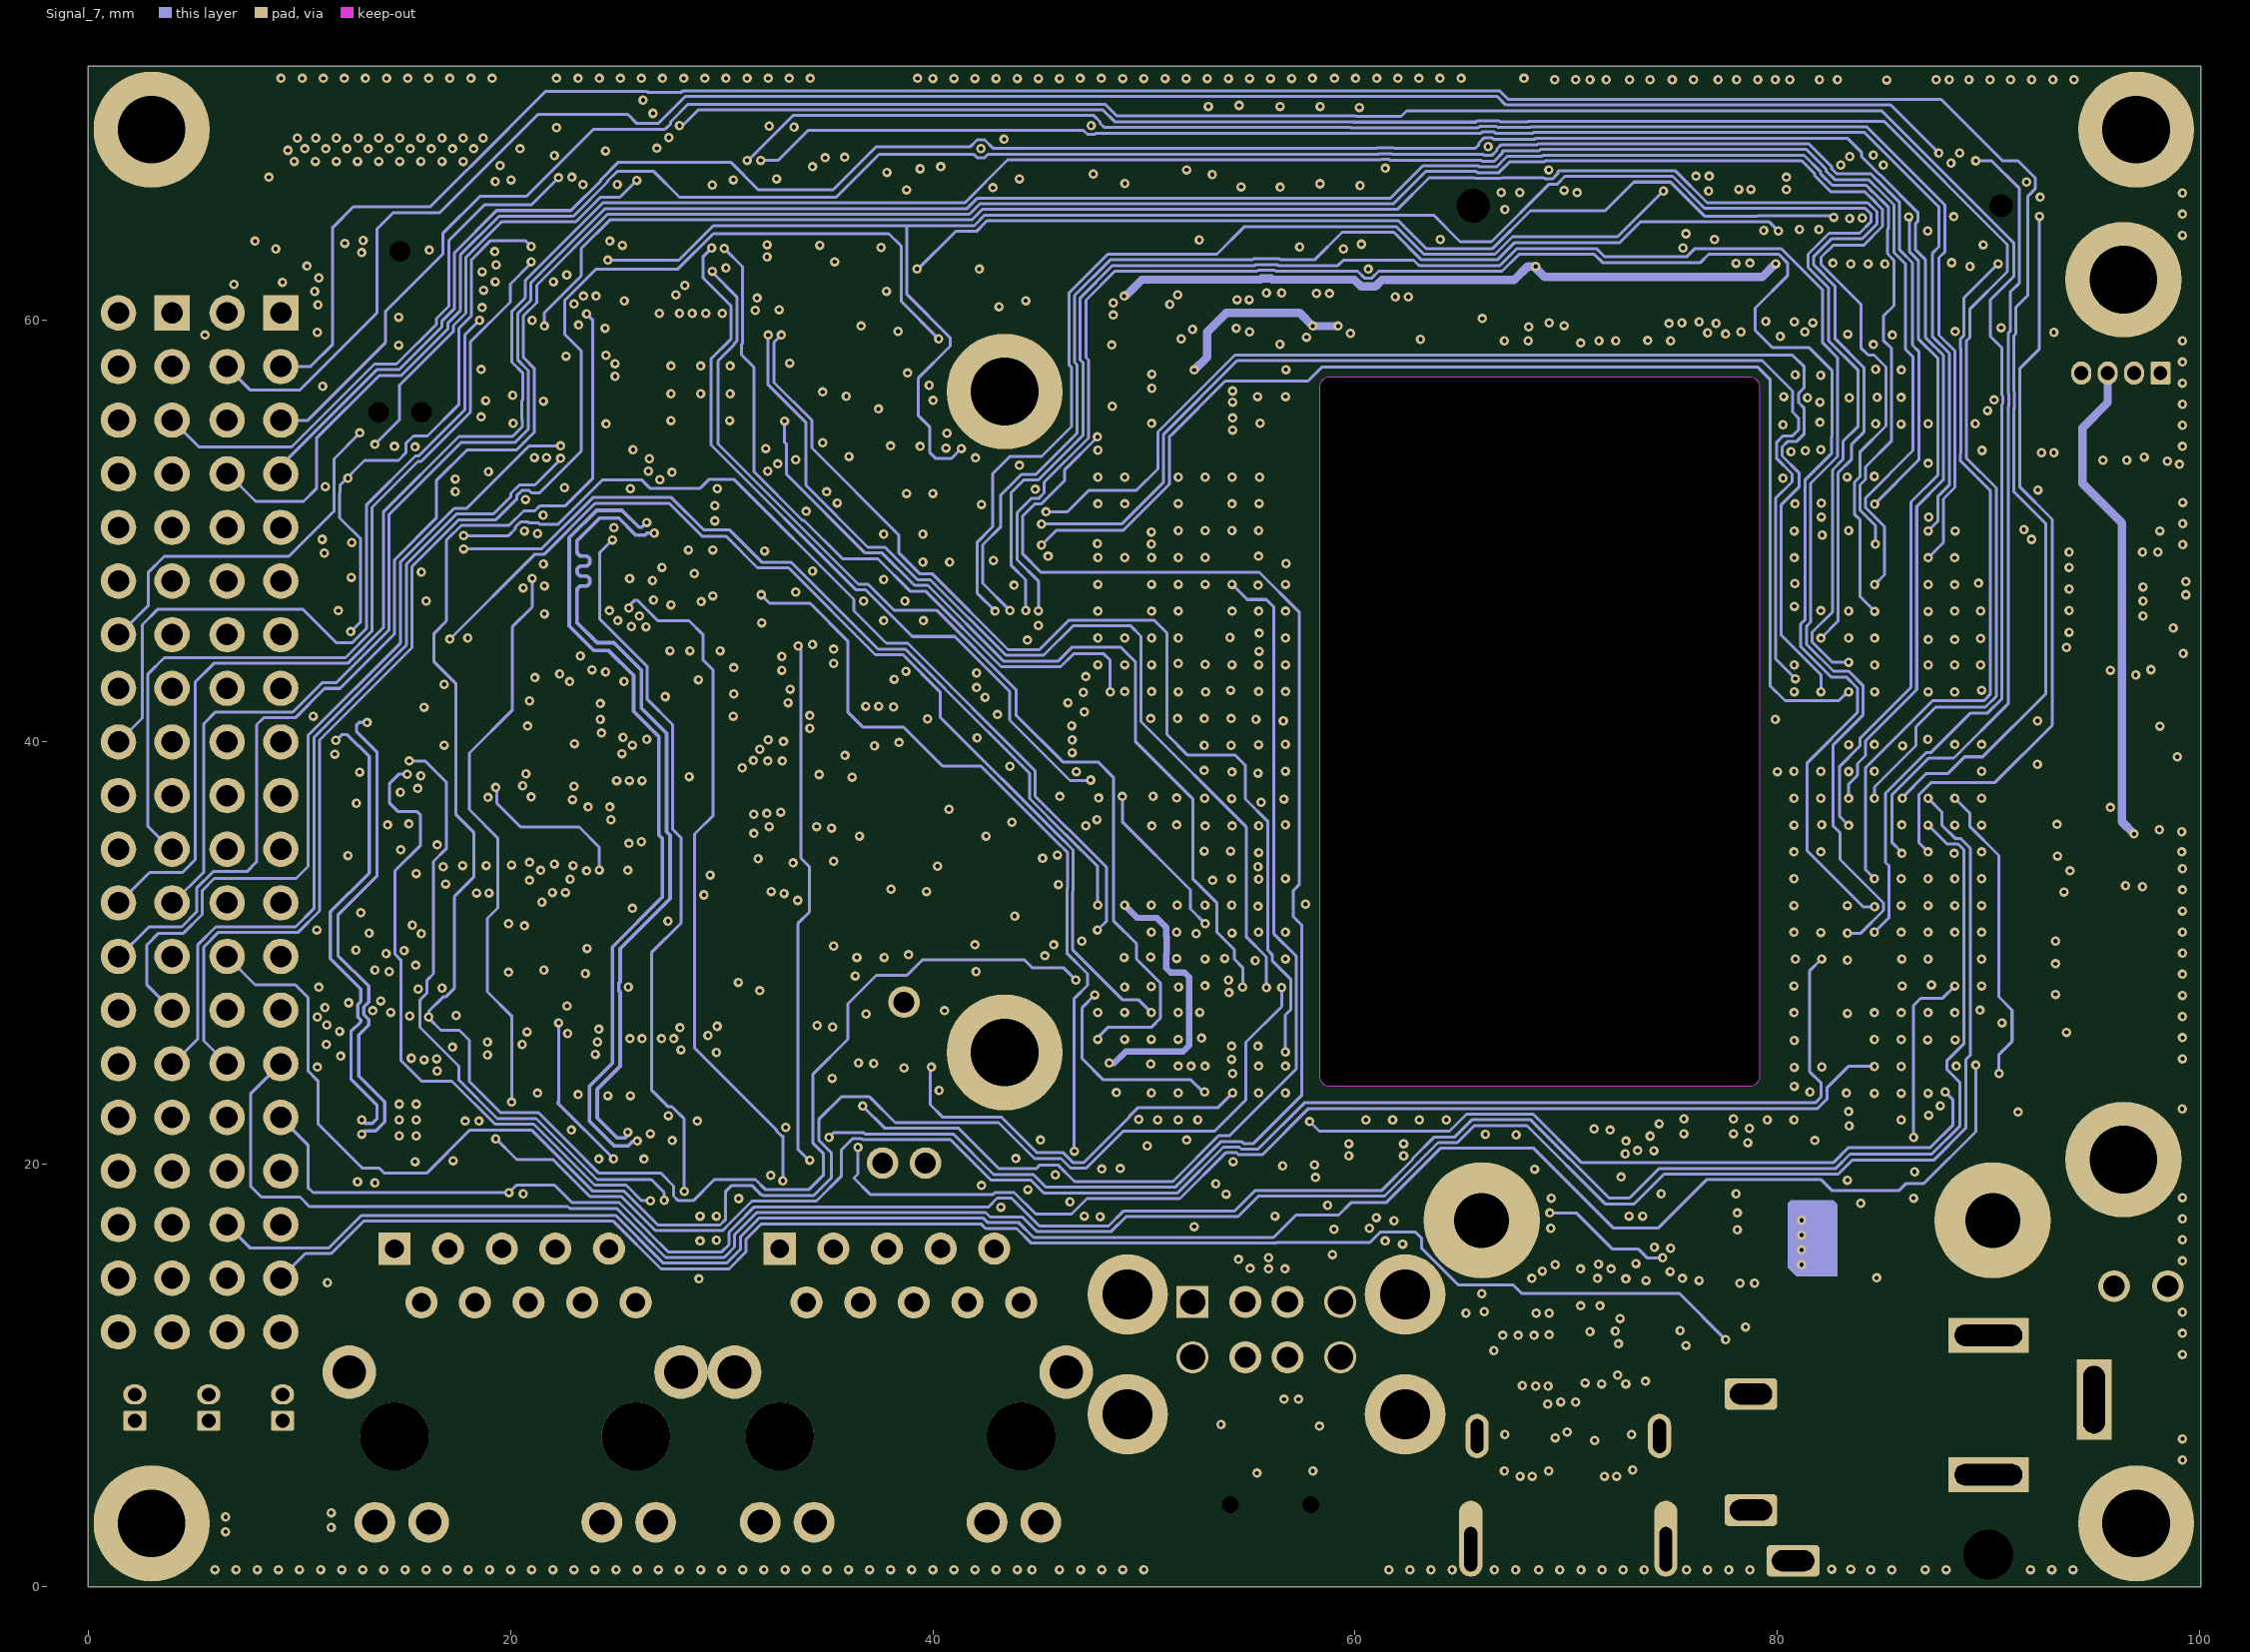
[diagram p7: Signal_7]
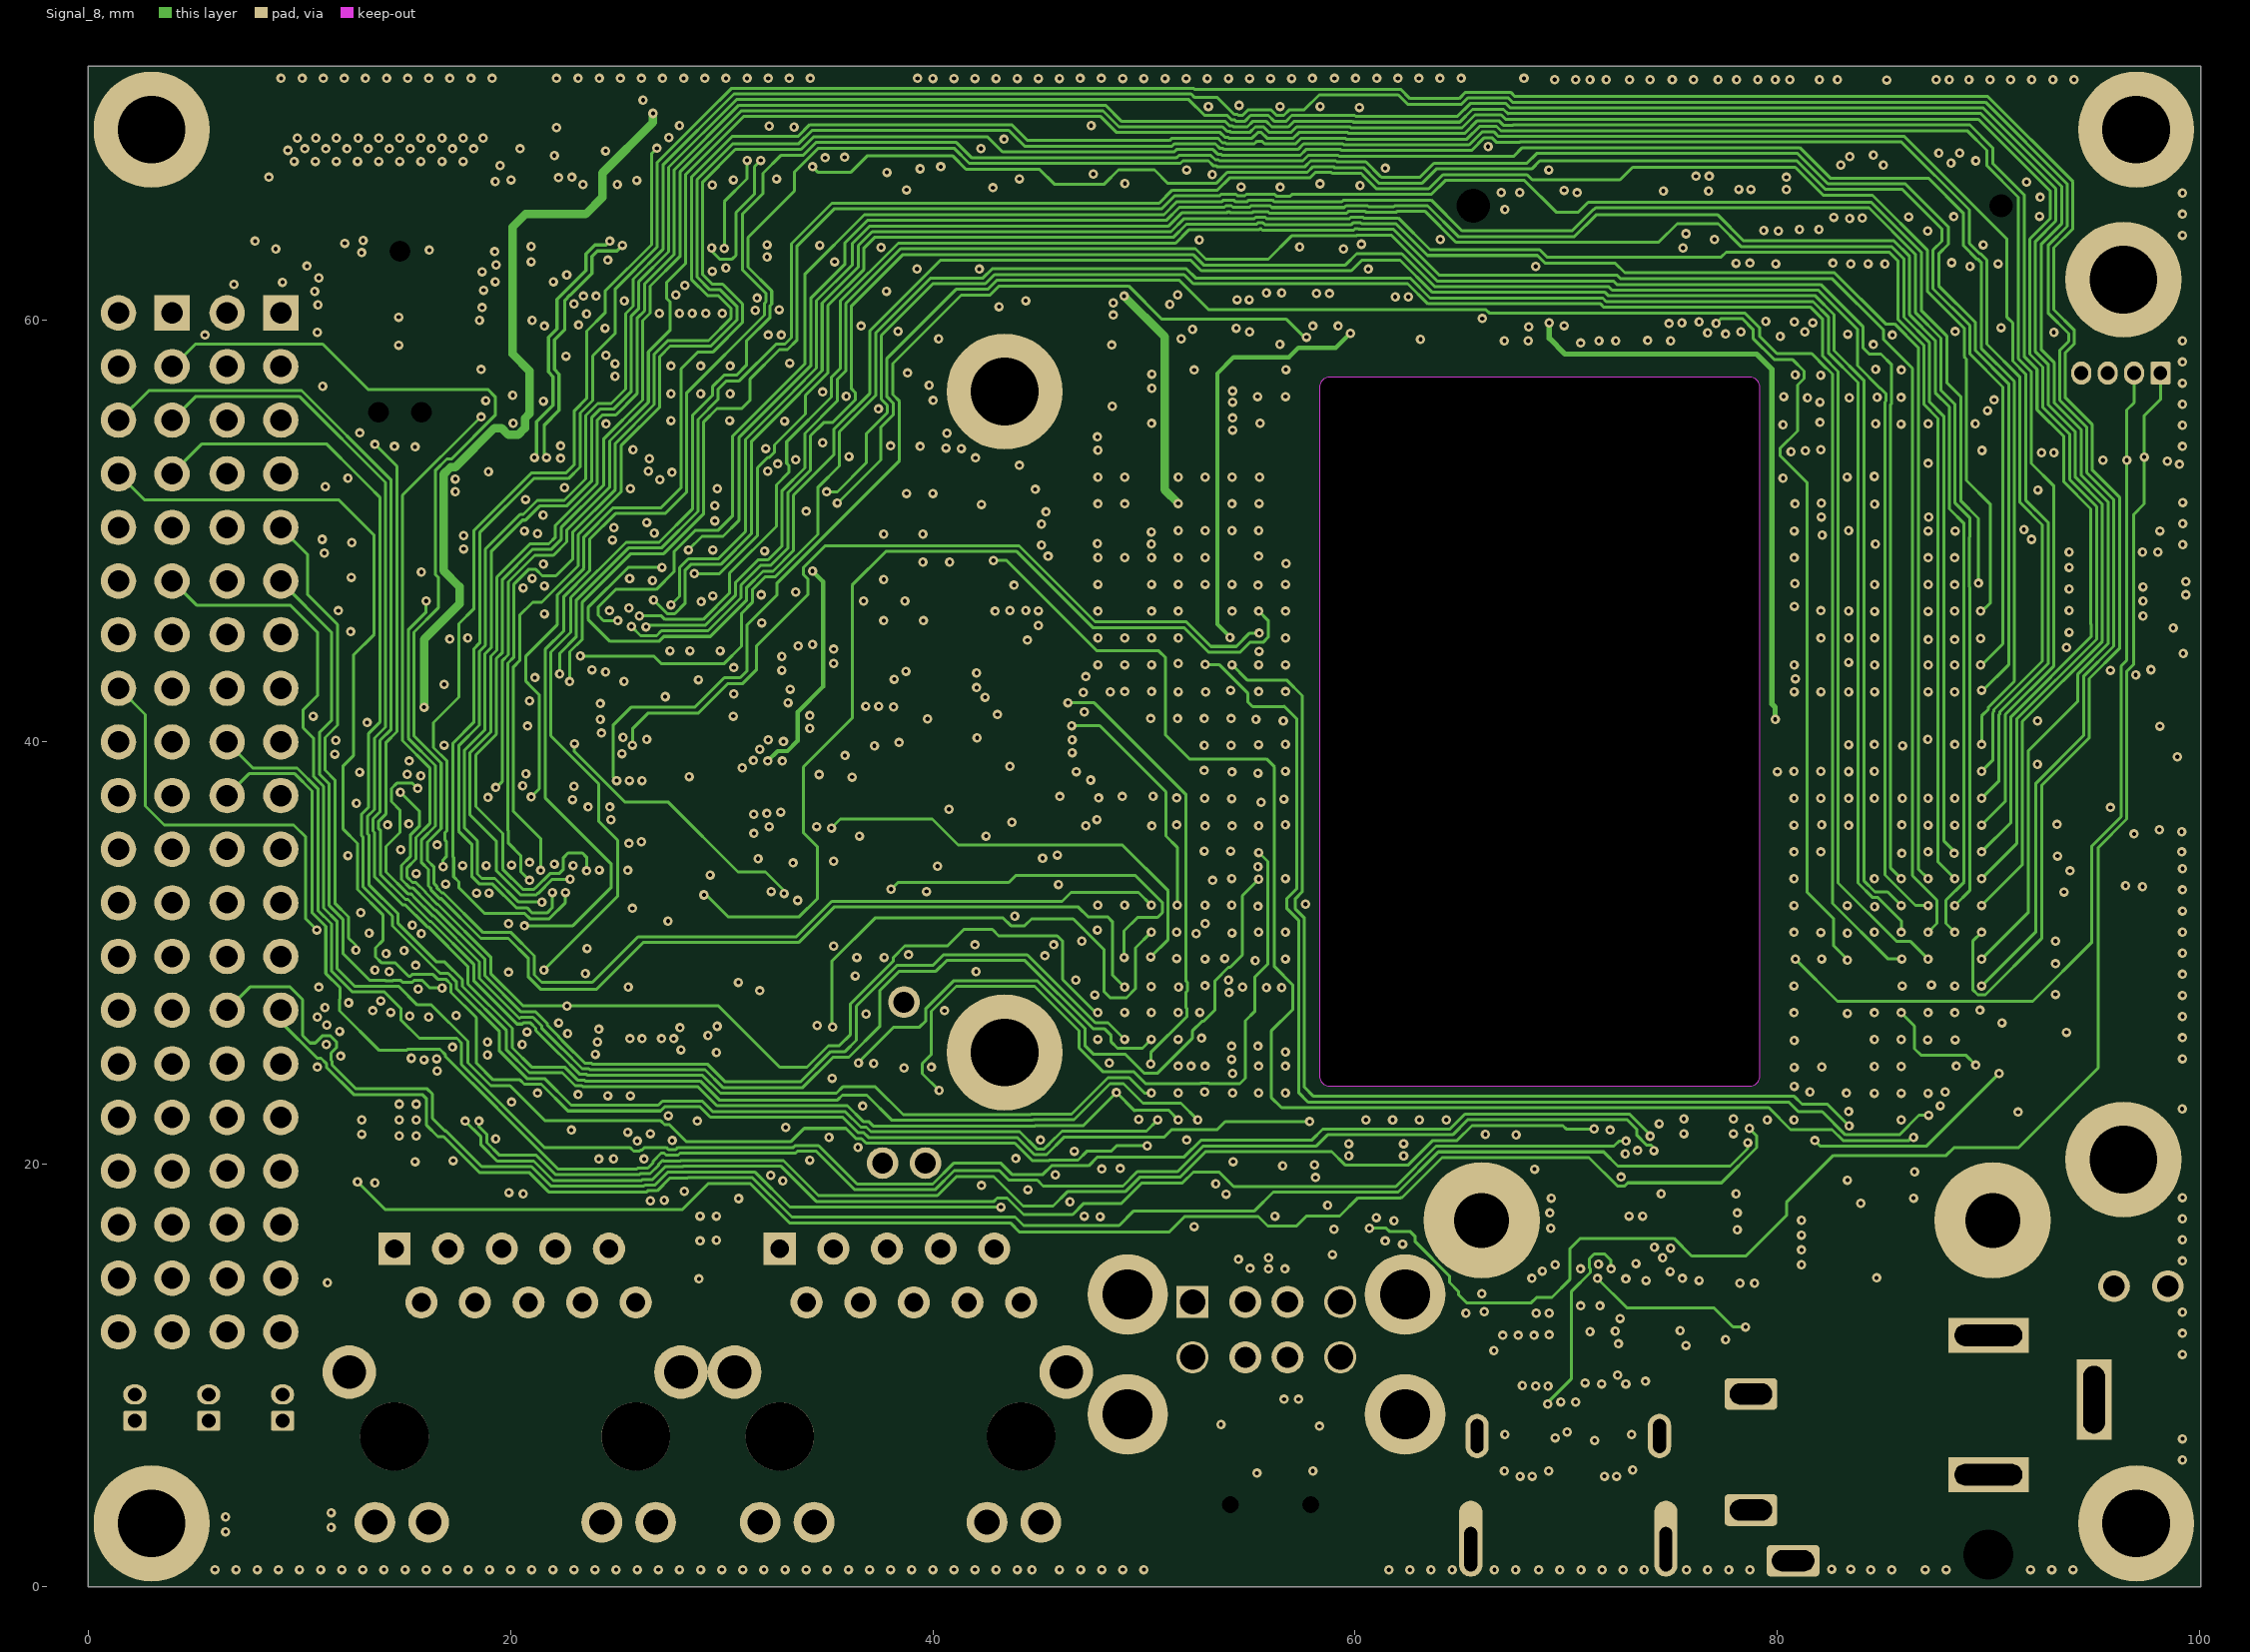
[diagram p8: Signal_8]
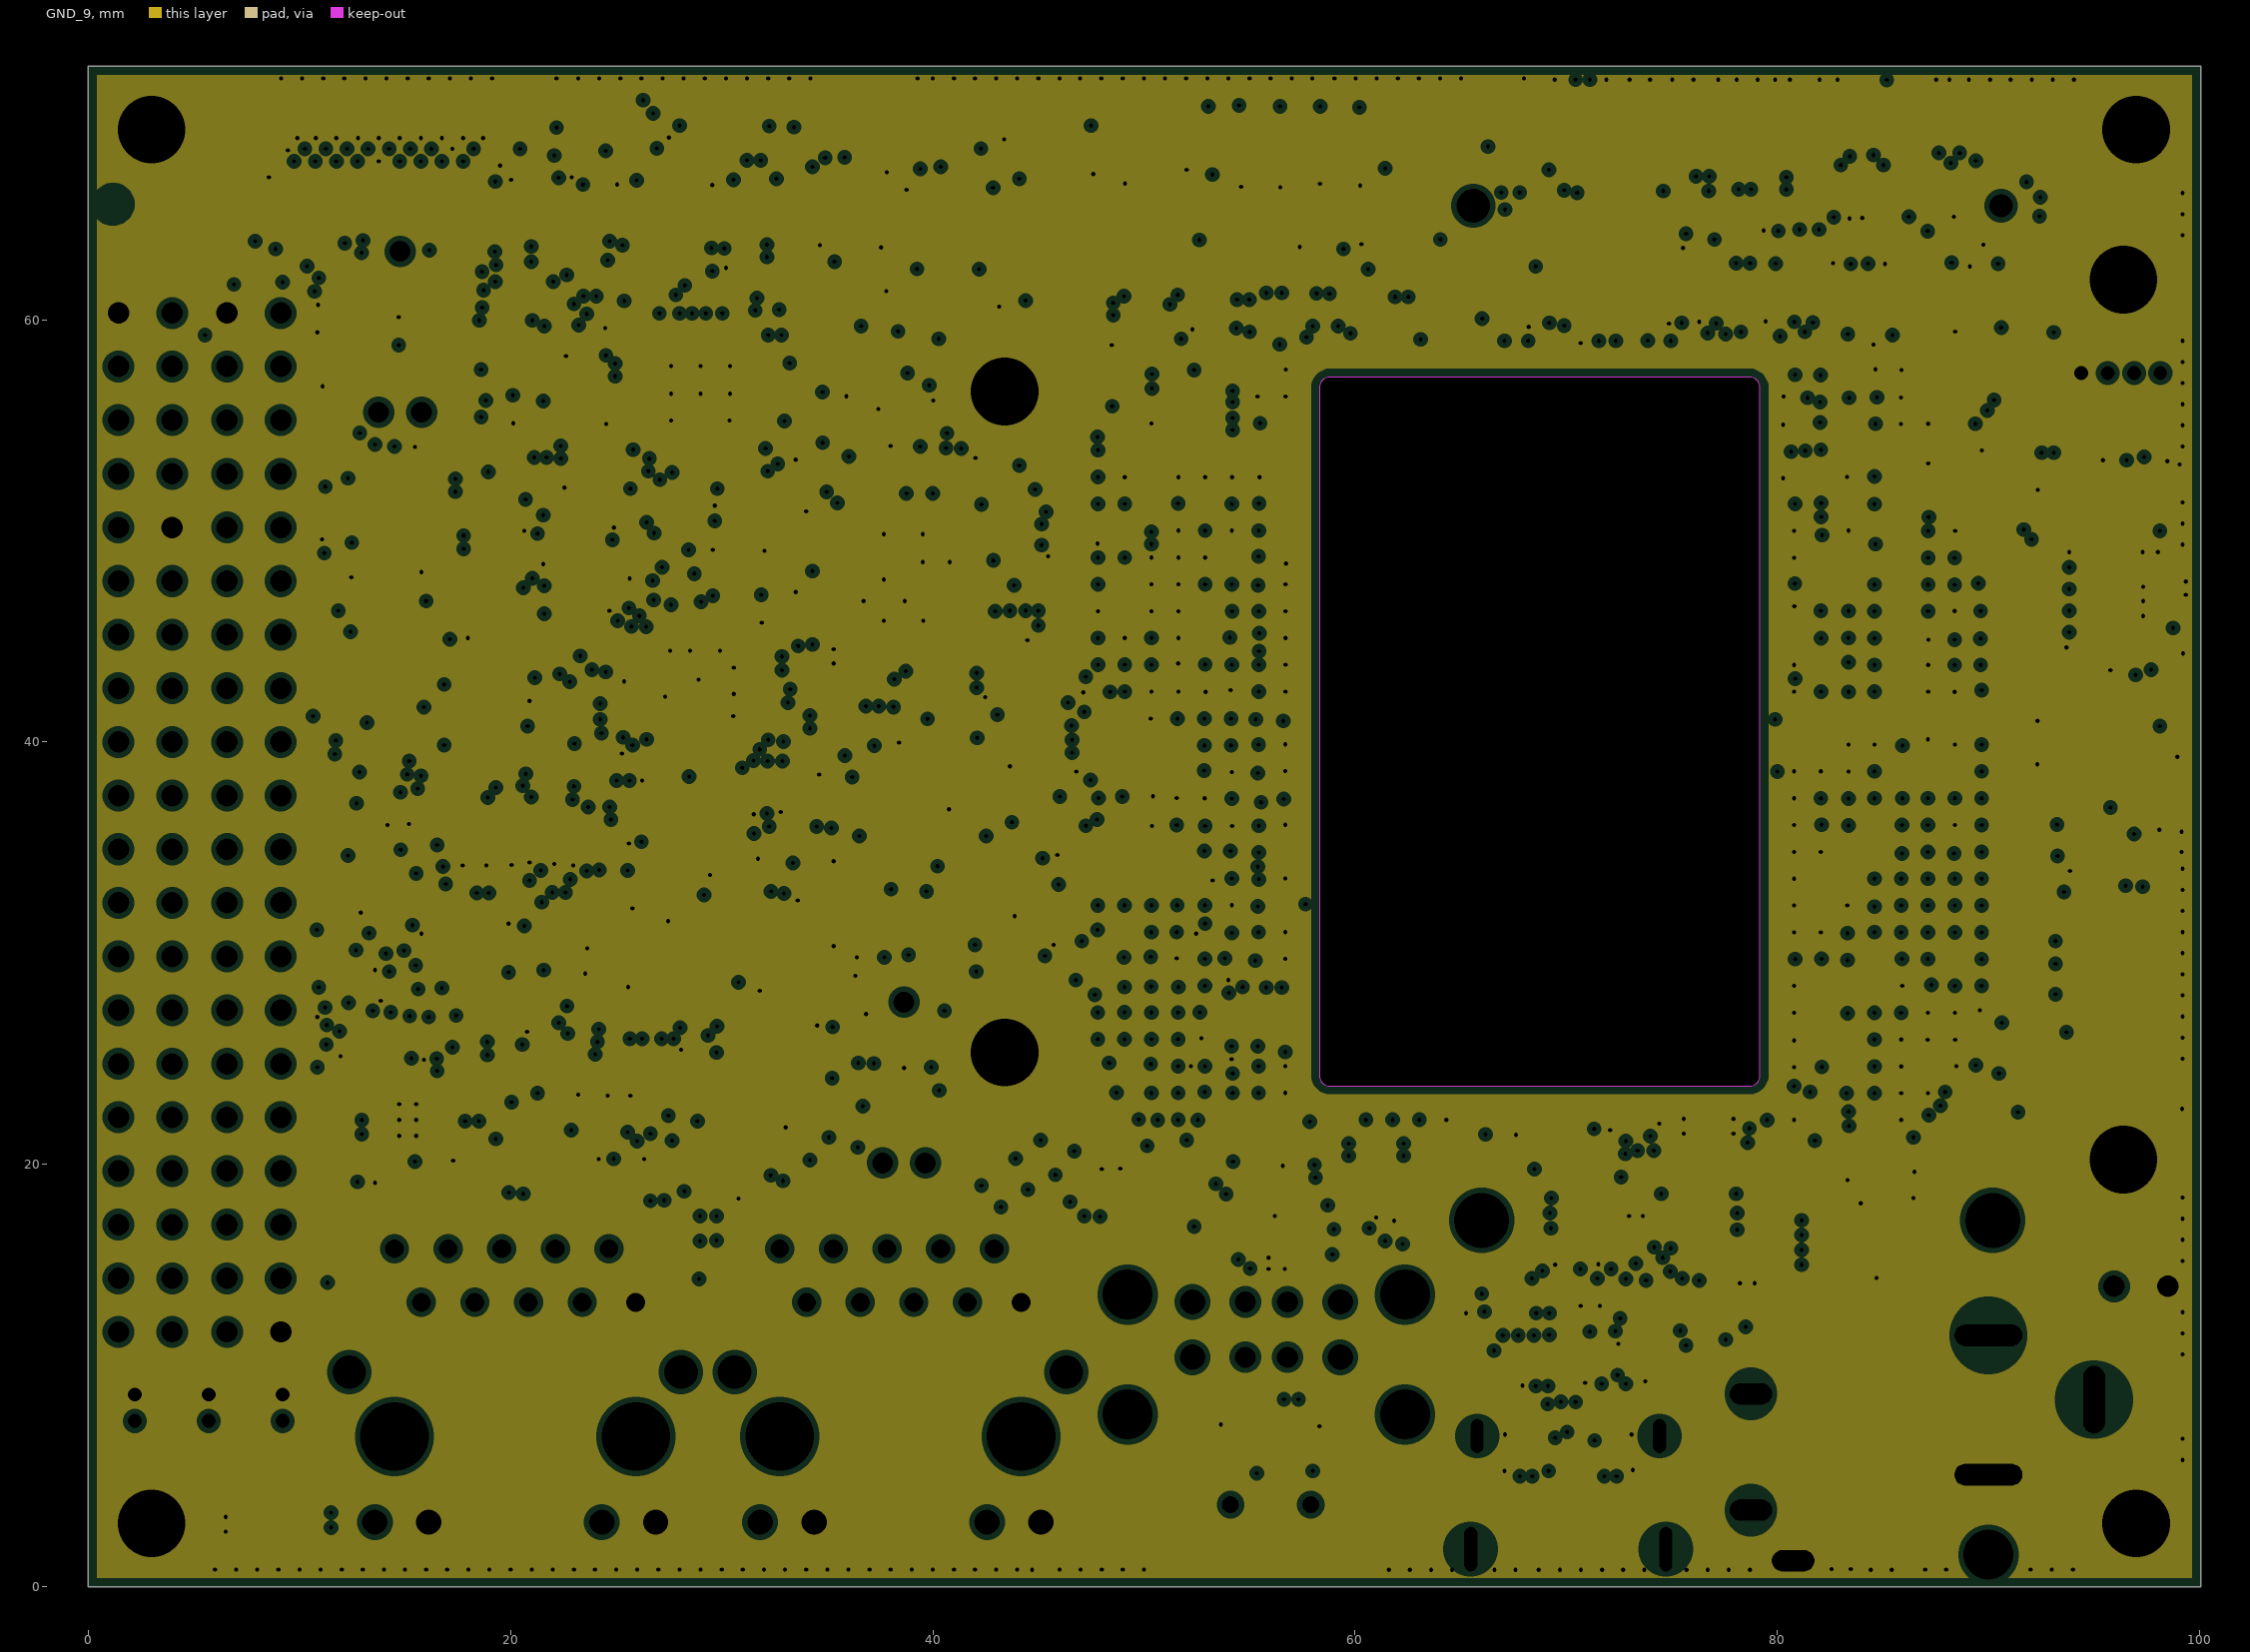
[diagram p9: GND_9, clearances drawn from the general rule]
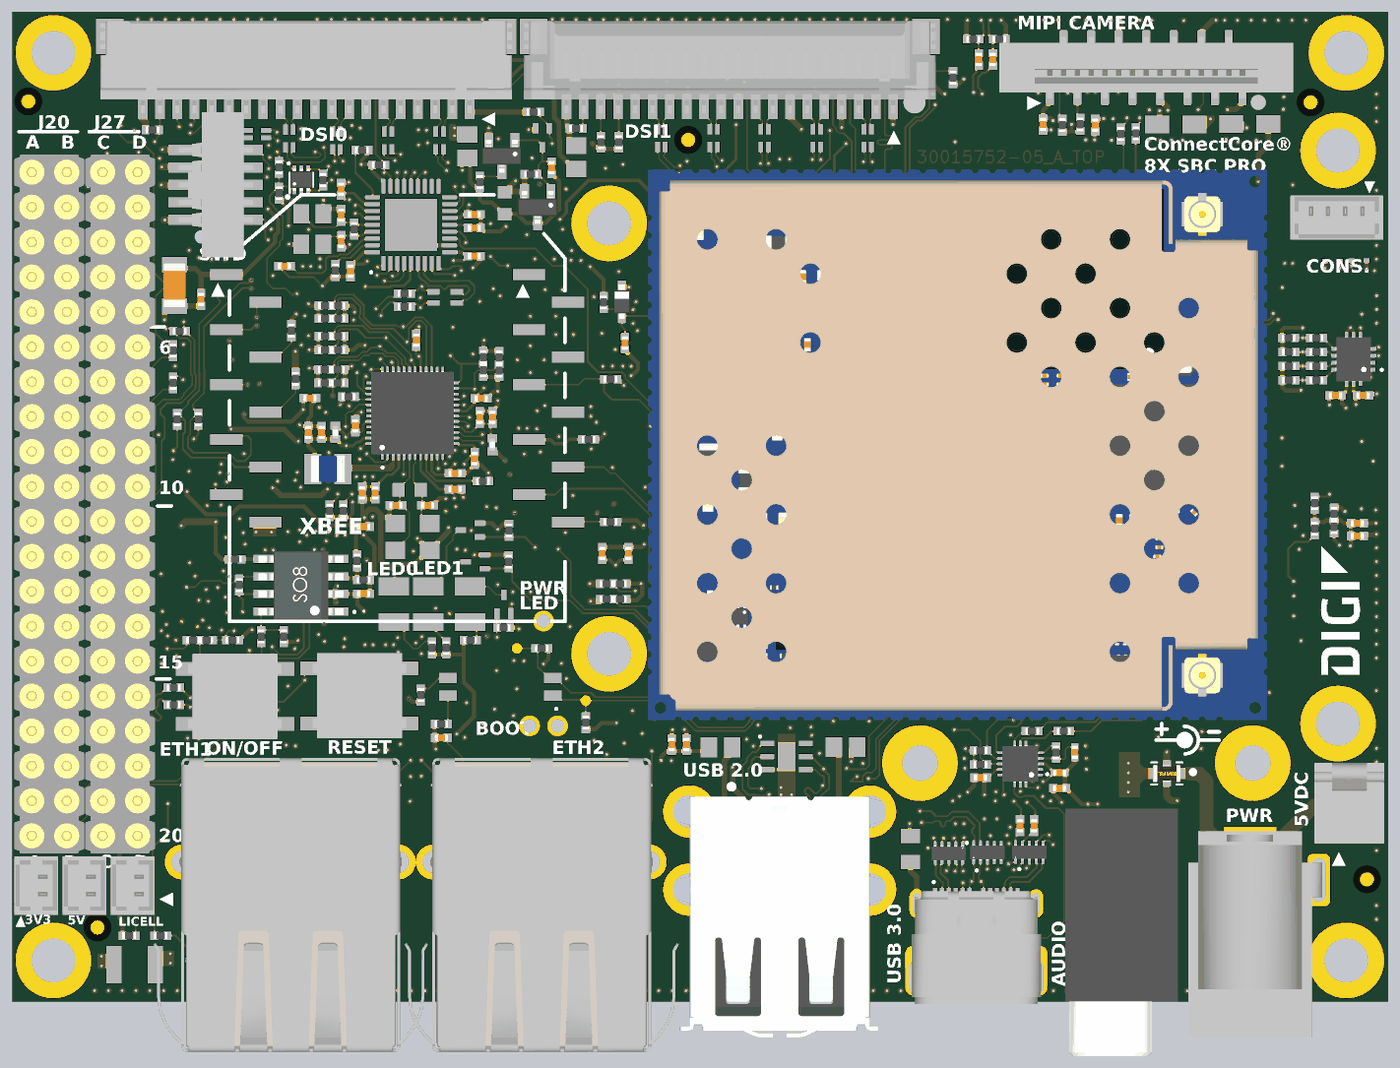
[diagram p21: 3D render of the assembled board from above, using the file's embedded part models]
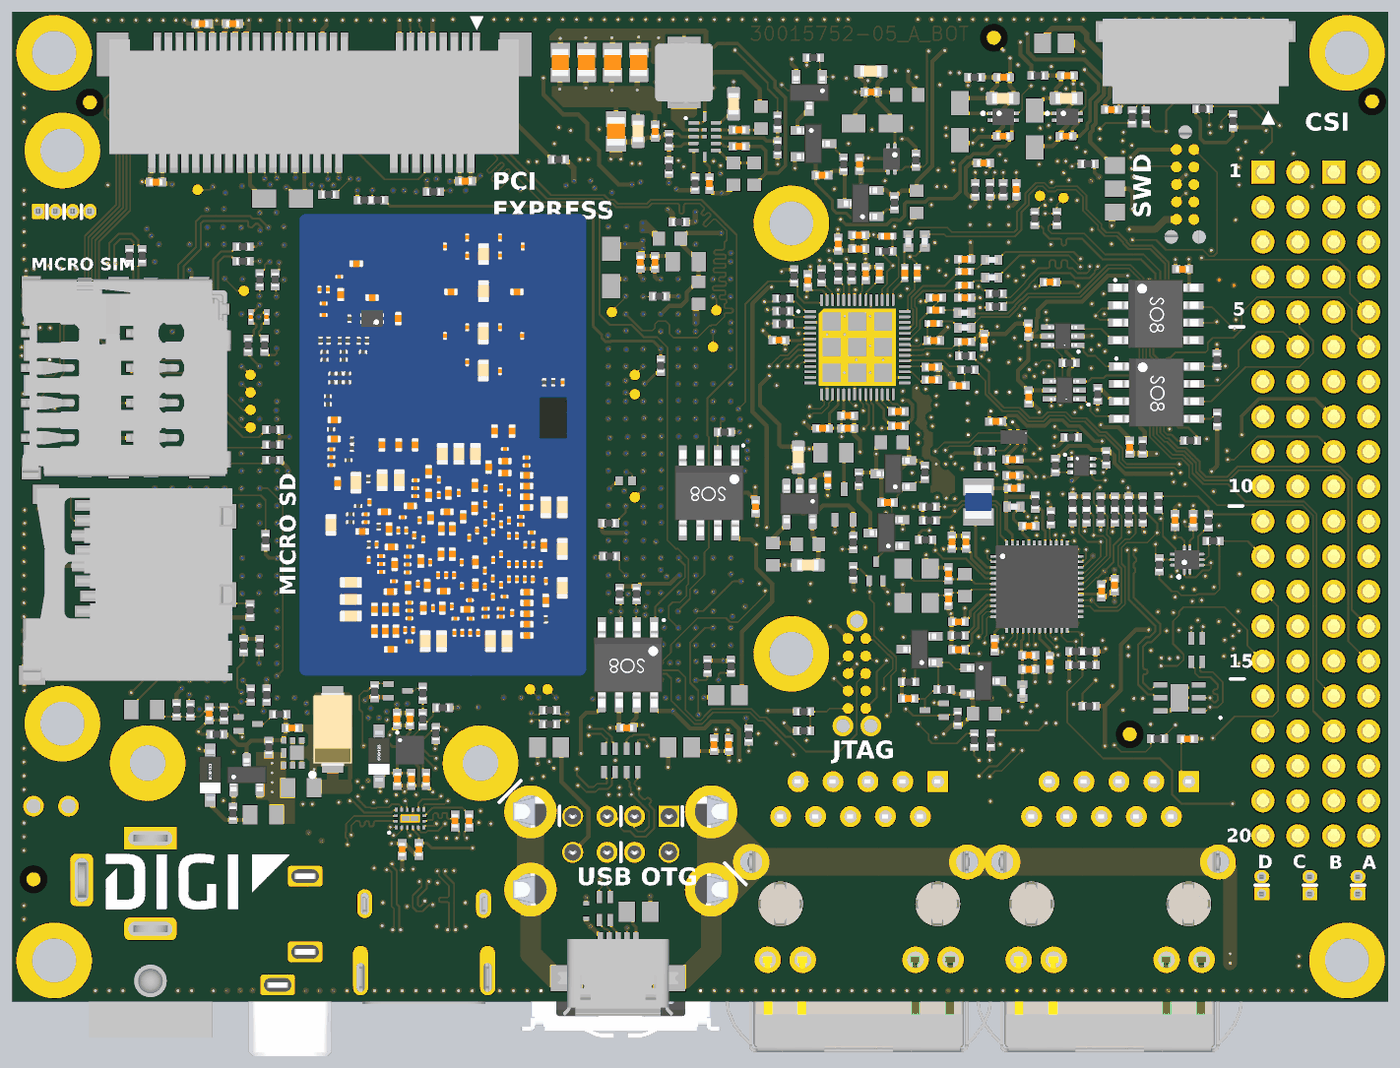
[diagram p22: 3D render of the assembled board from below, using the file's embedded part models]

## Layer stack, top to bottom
Top Solder: solder mask 0.0178, Dielectric, Dk 0
Top: signal copper 0.0518
Dielectric1: prepreg 0.0968, 2313, Dk 4.3
GND_2: plane copper 0.0127, net GND
Dielectric2: core 0.127, CORE, Dk 4.15
Signal_3: signal copper 0.0127
Dielectric3: prepreg 0.1123, 2116H, Dk 4.2
Signal_4: signal copper 0.0127
Dielectric 13: core 0.127, CORE, Dk 4.15
PWR_5: plane copper 0.0127, net (Multiple Nets)
Dielectric6: prepreg 0.3612, 7628 x 2, Dk 4.6
GND_6: plane copper 0.0127, net GND
Dielectric9: core 0.127, CORE, Dk 4.15
Signal_7: signal copper 0.0127
Dielectric10: prepreg 0.1123, 2116H, Dk 4.2
Signal_8: signal copper 0.0127
Dielectric 12: core 0.127, CORE, Dk 4.15
GND_9: plane copper 0.0127, net GND
Dielectric11: prepreg 0.0968, 2313, Dk 4.3
Bottom: signal copper 0.0518
Bottom Solder: solder mask 0.0178, Dielectric, Dk 0

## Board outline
0,0 0,72 100.05,72 100.05,0

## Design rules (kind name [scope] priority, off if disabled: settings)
AssemblyTestPointUsage [All] p1 off: valid=2
AssemblyTestpoint [All] p1 off: testpointundercomponent=TRUE minsize=1.016 maxsize=2.54 preferedsize=1.524 minholesize=0 maxholesize=1.016 preferedholesize=0.813 testpointgrid=0.025 usegrid=TRUE gridtolerance=0 allowsidetop=TRUE allowsidebottom=TRUE
BoardOutlineClearance [INNET ('*')] p1: gap=0.4 ignorepadtopadclearanceinfootprint=FALSE except(0.34: Via-OutlineEdge)
Clearance "2mm thru hole to SMT" [IsPad and inSMTComponent and onBottom vs IsThruPin And InThruComponent  And Not ((ObjectKind = 'Pad') And (Layer = 'MultiLayer') And (Net = 'No Net') And (PadIsPlated = 'False'))] p1: gap=2 ignorepadtopadclearanceinfootprint=FALSE except(0.2: Arc-Hole Track-Hole SMDPad-Hole THPad-Hole Via-Hole Fill-Hole Poly-Hole Region-Hole Text-Hole)
Clearance Clearance_Poly [InPoly] p2: gap=0.2 ignorepadtopadclearanceinfootprint=FALSE
Clearance Clearance_via-pad [isvia vs ispad] p3: gap=0 ignorepadtopadclearanceinfootprint=FALSE
Clearance Clearance_pad-pad [ispad vs ispad] p4: gap=0.3 ignorepadtopadclearanceinfootprint=TRUE except(0.2: Arc-Hole Track-Hole SMDPad-Hole THPad-Hole Via-Hole Fill-Hole Poly-Hole Region-Hole Text-Hole)
Clearance "Global Clearance" [All] p5: gap=0.127 ignorepadtopadclearanceinfootprint=FALSE except(0.2: Arc-Hole Track-Hole SMDPad-Hole THPad-Hole Via-Hole Fill-Hole Poly-Hole Region-Hole Text-Hole)
ComponentClearance [All] p1 off: gap=0.25 collisioncheckmode=3 verticalgap=0.25 showdistances=TRUE
DiffPairsRouting "ICD Stackup Planner 100ohm" [InDifferentialPairClass('100_Ohms')] p1: maxlimit=0.229 minlimit=0.206 mostfreqgap=0.206 toplayer_mingap=0.229 toplayer_prefgap=0.229 toplayer_minwidth=0.102 toplayer_maxwidth=0.102 toplayer_prefwidth=0.102 midlayer1_maxgap=0.206 midlayer1_minwidth=0.124 midlayer1_maxwidth=0.124 midlayer1_prefwidth=0.124 midlayer2_maxgap=0.206 midlayer2_minwidth=0.124 midlayer2_maxwidth=0.124 midlayer2_prefwidth=0.124 midlayer3_maxgap=0.206 midlayer3_minwidth=0.124 midlayer3_maxwidth=0.124 midlayer3_prefwidth=0.124 midlayer4_maxgap=0.206 midlayer4_minwidth=0.124 midlayer4_maxwidth=0.124 midlayer4_prefwidth=0.124 bottomlayer_mingap=0.229 bottomlayer_prefgap=0.229 bottomlayer_minwidth=0.102 bottomlayer_maxwidth=0.102 bottomlayer_prefwidth=0.102 maxuncoupledlength=20
DiffPairsRouting "ICD Stackup Planner 90ohm" [InDifferentialPairClass('90_Ohms')] p2: maxlimit=0.236 minlimit=0.211 mostfreqgap=0.211 toplayer_mingap=0.236 toplayer_prefgap=0.236 toplayer_minwidth=0.132 toplayer_maxwidth=0.132 toplayer_prefwidth=0.132 midlayer1_maxgap=0.211 midlayer1_minwidth=0.157 midlayer1_maxwidth=0.157 midlayer1_prefwidth=0.157 midlayer2_maxgap=0.211 midlayer2_minwidth=0.157 midlayer2_maxwidth=0.157 midlayer2_prefwidth=0.157 midlayer3_maxgap=0.211 midlayer3_minwidth=0.157 midlayer3_maxwidth=0.157 midlayer3_prefwidth=0.157 midlayer4_maxgap=0.211 midlayer4_minwidth=0.157 midlayer4_maxwidth=0.157 midlayer4_prefwidth=0.157 bottomlayer_mingap=0.236 bottomlayer_prefgap=0.236 bottomlayer_minwidth=0.132 bottomlayer_maxwidth=0.132 bottomlayer_prefwidth=0.132 maxuncoupledlength=20
DiffPairsRouting "ICD Stackup Planner 85ohm" [InDifferentialPairClass('85_Ohms')] p3: maxlimit=0.218 minlimit=0.193 mostfreqgap=0.193 toplayer_mingap=0.218 toplayer_prefgap=0.218 toplayer_minwidth=0.15 toplayer_maxwidth=0.15 toplayer_prefwidth=0.15 midlayer1_maxgap=0.193 midlayer1_minwidth=0.175 midlayer1_maxwidth=0.175 midlayer1_prefwidth=0.175 midlayer2_maxgap=0.193 midlayer2_minwidth=0.175 midlayer2_maxwidth=0.175 midlayer2_prefwidth=0.175 midlayer3_maxgap=0.193 midlayer3_minwidth=0.175 midlayer3_maxwidth=0.175 midlayer3_prefwidth=0.175 midlayer4_maxgap=0.193 midlayer4_minwidth=0.175 midlayer4_maxwidth=0.175 midlayer4_prefwidth=0.175 bottomlayer_mingap=0.218 bottomlayer_prefgap=0.218 bottomlayer_minwidth=0.15 bottomlayer_maxwidth=0.15 bottomlayer_prefwidth=0.15 maxuncoupledlength=20
FabricationTestPointUsage TestPointUsage [All] p1 off: valid=2 allowmultiple=FALSE
FabricationTestpoint Testpoint [All] p1 off: side=3 testpointundercomponent=TRUE minsize=1.016 maxsize=2.54 preferedsize=1.524 minholesize=0 maxholesize=1.016 preferedholesize=0.813 testpointgrid=0.025 allowsidetop=TRUE allowsidebottom=TRUE usegrid=TRUE gridtolerance=0
FanoutControl Fanout_BGA [IsBGA] p1 off: bgadir=Out bgaviamode=Centered fanoutstyle=Auto fanoutdirection=Alternating viagrid=0.025 // Fanout_BGA (Default Rule)
FanoutControl Fanout_Small [(CompPinCount < 5)] p4: bgadir=Out bgaviamode=Closest fanoutstyle=Auto fanoutdirection=OutThenIn viagrid=0.025 // Fanout_Small (Default Rule)
HoleSize [All] p1: absolutevalues=TRUE maxlimit=3.3 minlimit=0.2 maxpercent=80.000 minpercent=20.000
HoleToHoleClearance [All] p1: gap=0.25 allowstackedmicrovias=TRUE
MatchedLengths MatchedLengths_ETH1 [InDifferentialPairClass('ETH1')] p1: tolerance=2.5 checknetsindiffpair=FALSE checkdiffpairvsdiffpair=TRUE checkxsignals=TRUE checkothers=TRUE
MatchedLengths MatchedLengths_ETH2 [InDifferentialPairClass('ETH2')] p2: tolerance=2.5 checknetsindiffpair=FALSE checkdiffpairvsdiffpair=TRUE checkxsignals=TRUE checkothers=TRUE
MatchedLengths MatchedLengths_MIPI_CSI [InDifferentialPairClass('CSI')] p3: tolerance=2.5 checknetsindiffpair=FALSE checkdiffpairvsdiffpair=TRUE checkxsignals=TRUE checkothers=TRUE
MatchedLengths MatchedLengths_MIPI_DSI0 [InxSignalClass('MIPI_DSI0')] p4: tolerance=2.5 checknetsindiffpair=FALSE checkdiffpairvsdiffpair=TRUE checkxsignals=TRUE checkothers=TRUE
MatchedLengths MatchedLengths_MIPI_DSI1 [InxSignalClass('MIPI_DSI1')] p5: tolerance=2.5 checknetsindiffpair=FALSE checkdiffpairvsdiffpair=TRUE checkxsignals=TRUE checkothers=TRUE
MatchedLengths MatchedLengths_MIPI_CSI_GROUP [InxSignalClass('CSI')] p6: tolerance=2.5 checknetsindiffpair=FALSE checkdiffpairvsdiffpair=TRUE checkxsignals=TRUE checkothers=TRUE
MatchedLengths MatchedLengths_MIPI_CSI0_1 [InxSignalClass('MIPI_CSI')] p7: tolerance=2.5 checknetsindiffpair=FALSE checkdiffpairvsdiffpair=TRUE checkxsignals=TRUE checkothers=TRUE
MatchedLengths [InDifferentialPairClass('All Differential Pairs')] p8: tolerance=0.1 checknetsindiffpair=TRUE checkdiffpairvsdiffpair=FALSE checkxsignals=FALSE checkothers=FALSE
MinimumAnnularRing [All] p1 off: minimumring=0.127
MinimumSolderMaskSliver [All] p1 off: minsoldermaskwidth=0.1
PlaneClearance "3V3 PlaneClearance" [(InNamedPolygon('Layer 7 3V3'))] p1: clearance=0.25
PlaneClearance [All] p2: clearance=0.25
PlaneConnect "Via_ Direct_Connect_to_Plane" [IsVia] p1: planeconnectstyle=Direct reliefexpansion=0.508 reliefentries=4 reliefconductorwidth=0.254 reliefairgap=0.254
PlaneConnect [All] p2: planeconnectstyle=Relief reliefexpansion=0.2 reliefentries=4 reliefconductorwidth=0.25 reliefairgap=0.2
PolygonConnect Polysolid [All vs IsnamedPolygon('Polysolid')] p1: connectstyle=Direct reliefconductorwidth=0.254 reliefentries=4 polygonreliefangle="90 Angle" airgapwidth=0.254
PolygonConnect "Polygon To Via" [IsVia] p2: connectstyle=Direct reliefconductorwidth=0.254 reliefentries=4 polygonreliefangle="90 Angle" airgapwidth=0.254
PolygonConnect [All] p3: connectstyle=Relief reliefconductorwidth=0.25 reliefentries=4 polygonreliefangle="90 Angle" airgapwidth=0.2
RoutingCorners [All] p1: cornerstyle=45-Degree minsetback=2 maxsetback=2
RoutingVias "ICD Stackup Planner PTH Via 1" [All] p1: holewidth=0.25 width=0.56 viastyle="Through Hole" minholewidth=0.2 minwidth=0.457 maxholewidth=1 maxwidth=1.5 useviatemplates=TRUE viatemplateguid#1={D0C2CE42-2BFB-46EA-9632-C742B0E0D7E2} viatemplatename#1=v45h20m0mx0
SMDNeckDown [All] p1: percent=100.000
SilkToSilkClearance [All] p1 off: silktosilkclearance=0.125
SilkToSolderMaskClearance SilkscreenOverComponentPads [IsPad] p1 off: minsilkscreentomaskgap=0.125 clearancetoexposedcopper=TRUE
SolderMaskExpansion [All] p1: expansion=0.05
Width "Width Power" [InNetClass('Power')] p1: maxlimit=2 minlimit=0.127 preferedwidth=0.4 minimp=50.000000 maximp=50.000000 favimp=50.000000
Width [All] p2: maxlimit=0.158 minlimit=0.1 preferedwidth=0.142 toplayer_maxwidth=0.15 toplayer_prefwidth=0.127 midlayer1_minwidth=0.142 midlayer2_minwidth=0.142 midlayer3_minwidth=0.142 midlayer4_minwidth=0.142 bottomlayer_minwidth=0.127 bottomlayer_maxwidth=0.15 bottomlayer_prefwidth=0.127 minimp=50.000000 maximp=50.000000 favimp=50.000000
14 further rules are at their usual default settings.

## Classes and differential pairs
net class miniPCIe: PCIE_CLK_N PCIE_CLK_P PCIE_DIS_N PCIE_I2C_SCL PCIE_I2C_SDA PCIE_RESET_N PCIE_RX_N PCIE_RX_P PCIE_TX_N PCIE_TX_P PCIE_WAKE_N PCIECLK_N PCIECLK_P USB_PCIe_D_N USB_PCIe_D_P
net class "micro SD": NetC27_2 NetJ10_5 USDHC1_CD_B USDHC1_CLK USDHC1_CMD USDHC1_DATA0 USDHC1_DATA1 USDHC1_DATA2 USDHC1_DATA3
net class XBEE: MCA_UART2_CTS MCA_UART2_RTS MCA_UART2_RX MCA_UART2_TX XBEE_D_N XBEE_D_P XBEE_ON/SLEEP_N XBEE_RESET_N
net class SAI0: SAI0_RXD SAI0_TXC SAI0_TXD SAI0_TXFS
net class PCM: PCM_CLK PCM_IN PCM_OUT PCM_SYNC
net class RGMII2: "RGMII2_INT_ B" RGMII2_RD0 RGMII2_RD1 RGMII2_RD2 RGMII2_RD3 RGMII2_RESET_N RGMII2_RX_CTL RGMII2_RXC RGMII2_TD0 RGMII2_TD1 RGMII2_TD2 RGMII2_TD3 RGMII2_TX_CTL RGMII2_TXC RGMII_MDC_3V3 RGMII_MDIO_3V3
net class RGMII1: "RGMII1_INT_ B" RGMII1_RD0 RGMII1_RD1 RGMII1_RD2 RGMII1_RD3 RGMII1_RESET_N RGMII1_RX_CTL RGMII1_RXC RGMII1_TD0 RGMII1_TD1 RGMII1_TD2 RGMII1_TD3 RGMII1_TX_CTL RGMII1_TXC RGMII_MDC RGMII_MDC_3V3 RGMII_MDIO RGMII_MDIO_3V3
net class MIPI_CSIO: MIPI_CSI0_CLK_N MIPI_CSI0_CLK_P MIPI_CSI0_DATA0_N MIPI_CSI0_DATA0_P MIPI_CSI0_DATA1_N MIPI_CSI0_DATA1_P MIPI_CSI0_I2C0_SCL MIPI_CSI0_I2C0_SDA MIPI_CSI0_RESET_N
net class MIPI_DSI0: MIPI_DSI0_CLK_N MIPI_DSI0_CLK_P MIPI_DSI0_DATA0_N MIPI_DSI0_DATA0_P MIPI_DSI0_DATA1_N MIPI_DSI0_DATA1_P MIPI_DSI0_DATA2_N MIPI_DSI0_DATA2_P MIPI_DSI0_DATA3_N MIPI_DSI0_DATA3_P MIPI_DSI0_I2C0_SCL MIPI_DSI0_I2C0_SDA MIPI_DSI0_IRQ_N MIPI_DSI0_PWM0_OUT
net class MIPI_DSI1: MIPI_DSI1_CLK_N MIPI_DSI1_CLK_P MIPI_DSI1_DATA0_N MIPI_DSI1_DATA0_P MIPI_DSI1_DATA1_N MIPI_DSI1_DATA1_P MIPI_DSI1_DATA2_N MIPI_DSI1_DATA2_P MIPI_DSI1_DATA3_N MIPI_DSI1_DATA3_P MIPI_DSI1_I2C0_SCL MIPI_DSI1_I2C0_SDA MIPI_DSI1_IRQ_N MIPI_DSI1_PWM0_OUT
net class CSI: CSI_D00 CSI_D01 CSI_D02 CSI_D03 CSI_D04 CSI_D05 CSI_D06 CSI_D07 CSI_EN CSI_HSYNC CSI_MCLK CSI_PCLK CSI_RESET CSI_SCL CSI_SDA CSI_VSYNC
net class 5A: NetFIL1_1 VIN VIN_PROT
net class "micro SIM": PCIE_UIM_CLK PCIE_UIM_DATA PCIE_UIM_PWR PCIE_UIM_RST PCIE_UIM_VPP
component class "17 - History, Mechanicals": FIDUCIAL1 FIDUCIAL2 FIDUCIAL3 FIDUCIAL4 FIDUCIAL5 FIDUCIAL6 FIDUCIAL7 FIDUCIAL8 FIDUCIAL9 FIDUCIAL10 FIDUCIAL11 FIDUCIAL12 H1 H2 H3 H4
net class Power: 1V8 1V8_CODEC 1V8_EXT 3V3 3V3_CODEC 3V3_ETH 3V3_EXT 3V3_RF 3V3_USB 5V DVDDL1 DVDDL2 GND LDO3 NetC5_2 NetC7_1 NetC13_1 NetC13_2 NetC14_1 NetC27_2 NetC49_2 NetC56_2 NetC74_2 NetC85_2 NetC87_2 NetC90_2 NetC133_1 NetC135_2 NetC136_2 NetC142_1 NetC148_2 NetC155_1 NetC159_1 NetD2_2 NetD3_K NetD4_3 NetD8_A NetFIL1_1 NetJ14_20 NetJ16_20 NetJ18_A1 NetJ18_A4 NetJ18_B1 NetJ18_B4 NetJ23_7 NetJ28_5 NetL1_1 NetL3_1 NetL6_1 NetQ7_1 NetQ9_D NetR4_1 NetR26_1 NetR43_1 NetR45_2 NetR46_2 NetR49_1 NetR81_2 NetR219_2 NetR220_2 NetR221_2 NetR245_2 NetR247_1 NetR248_2 PCIE_VCC SHLD TCGND USBC_VBUS VCC_LICELL VCC_MCA VCC_SCU_1V8 VDDH1 VDDH2 VDDIO1 VDDIO2 VIN VIN_PROT VLDO4_1V5 VSYS XBEE_VCC
component class "06 - JTAG, SWD, MicroSD, Mini PCIe, MicroSIM": C10 C11 C12 C13 C14 C15 C16 C17 C18 C19 C20 C21 C22 C23 C24 C25 C26 C27 C28 C46 C64 C135 C136 C139 C140 CAD1 CAD2 J7 J8 J9 J10 L1 R14 R29 R30 R43 R44 R45 R46 R47 R48 R49 R50 R51 R52 R53 R54 R55 R56 R57 R58 R110 R111 R112 R117 R195 R217 R218 R236 R237 U3 U28
component class "02 - CCIMX8X Power, Control, MCA": C154 C155 C156 C157 C158 C159 C160 C161 C162 D13 R1 R2 R3 R4 R5 R6 R7 R8 R9 R205 R219 R220 R221 R230 R231 R256 R257 R258 R259 R260 TP1 TP2 TP3 TP4 TP5 TP6 TP7 TP8 TP9 TP10 U1 U32 U33
component class "05 - Power, bootstrap, reset": C1 C2 C3 C4 C5 C6 C7 C8 C9 C132 C142 C143 D3 D4 D5 D14 FIL1 J2 J3 J4 J5 J6 Q1 Q7 Q8 R13 R15 R17 R18 R19 R20 R21 R22 R23 R24 R25 R26 R27 R28 R31 R32 R33 R34 R35 R36 R37 R38 R39 R40 R41 R42 R64 R162 R213 R216 R255 S2 SW1 SW2 TP13 TP14 U2 U26 U27
component class "12 - USB Type C, USB microAB": C98 C99 C100 C101 C102 C103 C104 C105 C106 C107 C108 C147 C148 C149 C150 C151 C152 C153 D1 D2 D8 D9 D10 J19 J28 L37 L38 L39 Q4 R147 R148 R149 R150 R151 R152 R153 R214 R234 R235 U17 U18 U19 U31
component class "08 - Ethernet1": C41 C42 C43 C44 C45 C47 C48 C49 C50 C51 C52 C53 C54 C55 C56 C57 C58 C59 C62 J12 L2 L3 L4 Q2 Q11 R16 R69 R70 R71 R72 R73 R74 R75 R81 R82 R83 R84 R85 R86 R87 R88 R89 R90 R91 R92 R93 R94 R95 R96 R97 R98 R99 R100 R101 R102 R160 R244 U9 U11 U23 U29 X1
component class "11 - USB HUB": C81 C82 C83 C84 C85 C86 C87 C88 C89 C90 C91 C92 C93 C94 C95 C96 C97 J18 L9 L10 L11 L12 L13 L14 L15 L29 L30 Q3 Q12 R12 R76 R77 R78 R79 R135 R136 R137 R138 R139 R140 R141 R142 R143 R144 R145 R146 R161 R191 R192 R228 R229 R238 R239 R242 R243 U13 U14 U15 U16 U24 X3
component class "10 - Displays and cameras": C78 C80 J14 J15 J16 J17 L8 L24 L25 L26 L27 L28 L31 L32 L33 L34 L35 L36 R134 R215 R251 R252 R253 R254 U22
component class "13 - Audio": C34 C35 C36 C79 C109 C110 C111 C112 C113 C114 C115 C116 C117 C118 C119 C120 C121 C122 C123 C124 C125 C126 C127 C128 C129 C130 C131 C133 C134 J21 L16 L17 L18 L19 L20 L21 NT1 Q5 Q6 Q9 Q10 R154 R155 R156 R157 R158 R159 R164 R165 R166 R167 R168 R169 R170 R193 R194 R199 U20 U21 U25
component class "14 - I2C, XBee": C37 C38 J22 J23 L22 L23 R171 R172 R173 R174 R175 R176 R177 R178 R185 R186 R187 R188 R189 R190 R196 R197 R198 R240 R241
component class "15 - Expansion connectors, User LEDs, RF signals": D11 D12 J20 J27 Q13 Q14 R108 R109 R203 R204
net class DIFF90: EXPANSION_USB1_D_N EXPANSION_USB1_D_P EXPANSION_USB2_D_N EXPANSION_USB2_D_P NetL9_1 NetL9_4 NetL10_1 NetL10_4 NetL11_1 NetL11_4 NetL12_1 NetL12_4 OTGD_N OTGD_P PCIe/EXPANSION_USB1_D_N PCIe/EXPANSION_USB1_D_P SS3_1_RX_N SS3_1_RX_P SS3_1_TX_N SS3_1_TX_P SS3_2_RX_N SS3_2_RX_P SS3_2_TX_N SS3_2_TX_P SS_1_TX_N SS_1_TX_P SS_2_TX_N SS_2_TX_P USB_OTG1_N USB_OTG1_P USB_OTG2_N USB_OTG2_P USB_PCIe_D_N USB_PCIe_D_P USB_SS3_RX_N USB_SS3_RX_P USB_SS3_TX_N USB_SS3_TX_P USBH1_D_N USBH1_D_P USBH2_D_N USBH2_D_P XBEE/EXPANSION_USB2_D_N XBEE/EXPANSION_USB2_D_P XBEE_D_N XBEE_D_P
component class "03 - CCIMX8X Digital interfaces": R179 R180 R181 R182 R183 R184 R232 TP15 TP16
component class "04 - CCIMX8X RF, PCIe": C137 C138 R10 R222 R223 R224 R225 R226 R227 TP18 TP19 TP20 TP21
component class "07 - Console, UART, CAN": C29 C30 C31 C32 C33 C39 C40 C145 C146 D6 D7 J11 R11 R59 R60 R61 R62 R63 R65 R66 R67 R68 R163 R233 R245 R246 R247 R248 R249 R250 U4 U5 U6 U7 U8 U10
component class "09 - Ethernet2": C60 C61 C63 C65 C66 C67 C68 C69 C70 C71 C72 C73 C74 C75 C76 C77 J13 L5 L6 L7 R80 R103 R104 R105 R106 R107 R113 R114 R115 R116 R118 R119 R120 R121 R122 R123 R124 R125 R126 R127 R128 R129 R130 R131 R132 R133 U12 X2
net class DIFF85: NetR222_2 NetR223_2 NetR224_2 NetR225_2 NetR226_2 NetR227_2 PCIE_CLK_N PCIE_CLK_P PCIE_RX_N PCIE_RX_P PCIE_SOM_CLK_N PCIE_SOM_CLK_P PCIE_TX_N PCIE_TX_P PCIECLK_N PCIECLK_P PCIETX_N PCIETX_P
net class DIFF100: ETH1_TXRXA_N ETH1_TXRXA_P ETH1_TXRXB_N ETH1_TXRXB_P ETH1_TXRXC_N ETH1_TXRXC_P ETH1_TXRXD_N ETH1_TXRXD_P ETH2_TXRXA_N ETH2_TXRXA_P ETH2_TXRXB_N ETH2_TXRXB_P ETH2_TXRXC_N ETH2_TXRXC_P ETH2_TXRXD_N ETH2_TXRXD_P MIPI_CSI0_CLK_N MIPI_CSI0_CLK_P MIPI_CSI0_DATA0_N MIPI_CSI0_DATA0_P MIPI_CSI0_DATA1_N MIPI_CSI0_DATA1_P MIPI_DSI0_CLK_N MIPI_DSI0_CLK_P MIPI_DSI0_DATA0_N MIPI_DSI0_DATA0_P MIPI_DSI0_DATA1_N MIPI_DSI0_DATA1_P MIPI_DSI0_DATA2_N MIPI_DSI0_DATA2_P MIPI_DSI0_DATA3_N MIPI_DSI0_DATA3_P MIPI_DSI1_CLK_N MIPI_DSI1_CLK_P MIPI_DSI1_DATA0_N MIPI_DSI1_DATA0_P MIPI_DSI1_DATA1_N MIPI_DSI1_DATA1_P MIPI_DSI1_DATA2_N MIPI_DSI1_DATA2_P MIPI_DSI1_DATA3_N MIPI_DSI1_DATA3_P NetJ14_2 NetJ14_3 NetJ14_5 NetJ14_6 NetJ14_8 NetJ14_9 NetJ14_11 NetJ14_12 NetJ14_14 NetJ14_15 NetJ16_2 NetJ16_3 NetJ16_5 NetJ16_6 NetJ16_8 NetJ16_9 NetJ16_11 NetJ16_12 NetJ16_14 NetJ16_15
differential pair SS_2_TX: +SS_2_TX_P -SS_2_TX_N
differential pair SS_1_TX: +SS_1_TX_P -SS_1_TX_N
differential pair XBEE/EXPANSION_USB2_D: +XBEE/EXPANSION_USB2_D_P -XBEE/EXPANSION_USB2_D_N
differential pair PCIe/EXPANSION_USB1_D: +PCIe/EXPANSION_USB1_D_P -PCIe/EXPANSION_USB1_D_N
differential pair EXPANSION_USB2_D: +EXPANSION_USB2_D_P -EXPANSION_USB2_D_N
differential pair EXPANSION_USB1_D: +EXPANSION_USB1_D_P -EXPANSION_USB1_D_N
differential pair XBEE_D: +XBEE_D_P -XBEE_D_N
differential pair USB_PCIe_D: +USB_PCIe_D_P -USB_PCIe_D_N
differential pair SPKR: +SPKR_P -SPKR_N
differential pair SPKL: +SPKL_P -SPKL_N
differential pair USBH1_D: +USBH1_D_P -USBH1_D_N
differential pair USBH2_D: +USBH2_D_P -USBH2_D_N
differential pair ETH1_TXRXA: +ETH1_TXRXA_P -ETH1_TXRXA_N
differential pair ETH1_TXRXB: +ETH1_TXRXB_P -ETH1_TXRXB_N
differential pair ETH1_TXRXC: +ETH1_TXRXC_P -ETH1_TXRXC_N
differential pair ETH1_TXRXD: +ETH1_TXRXD_P -ETH1_TXRXD_N
differential pair ETH2_TXRXA: +ETH2_TXRXA_P -ETH2_TXRXA_N
differential pair ETH2_TXRXB: +ETH2_TXRXB_P -ETH2_TXRXB_N
differential pair ETH2_TXRXC: +ETH2_TXRXC_P -ETH2_TXRXC_N
differential pair ETH2_TXRXD: +ETH2_TXRXD_P -ETH2_TXRXD_N
differential pair MIPI_CSI0_CLK: +MIPI_CSI0_CLK_P -MIPI_CSI0_CLK_N
differential pair MIPI_CSI0_DATA0: +MIPI_CSI0_DATA0_P -MIPI_CSI0_DATA0_N
differential pair MIPI_CSI0_DATA1: +MIPI_CSI0_DATA1_P -MIPI_CSI0_DATA1_N
differential pair MIPI_DSI0_CLK: +MIPI_DSI0_CLK_P -MIPI_DSI0_CLK_N
differential pair MIPI_DSI0_DATA0: +MIPI_DSI0_DATA0_P -MIPI_DSI0_DATA0_N
differential pair MIPI_DSI0_DATA1: +MIPI_DSI0_DATA1_P -MIPI_DSI0_DATA1_N
differential pair MIPI_DSI0_DATA2: +MIPI_DSI0_DATA2_P -MIPI_DSI0_DATA2_N
differential pair MIPI_DSI0_DATA3: +MIPI_DSI0_DATA3_P -MIPI_DSI0_DATA3_N
differential pair MIPI_DSI1_CLK: +MIPI_DSI1_CLK_P -MIPI_DSI1_CLK_N
differential pair MIPI_DSI1_DATA0: +MIPI_DSI1_DATA0_P -MIPI_DSI1_DATA0_N
differential pair MIPI_DSI1_DATA1: +MIPI_DSI1_DATA1_P -MIPI_DSI1_DATA1_N
differential pair MIPI_DSI1_DATA2: +MIPI_DSI1_DATA2_P -MIPI_DSI1_DATA2_N
differential pair MIPI_DSI1_DATA3: +MIPI_DSI1_DATA3_P -MIPI_DSI1_DATA3_N
differential pair PCIE_CLK: +PCIE_CLK_P -PCIE_CLK_N
differential pair PCIE_RX: +PCIE_RX_P -PCIE_RX_N
differential pair PCIE_TX: +PCIE_TX_P -PCIE_TX_N
differential pair PCIECLK: +PCIECLK_P -PCIECLK_N
differential pair PCIETX: +PCIETX_P -PCIETX_N
differential pair SS3_1_RX: +SS3_1_RX_P -SS3_1_RX_N
differential pair SS3_2_RX: +SS3_2_RX_P -SS3_2_RX_N
differential pair USB_SS3_RX: +USB_SS3_RX_P -USB_SS3_RX_N
differential pair USB_SS3_TX: +USB_SS3_TX_P -USB_SS3_TX_N
differential pair OTGD: +OTGD_P -OTGD_N
differential pair PCIE_SOM_CLK: +PCIE_SOM_CLK_P -PCIE_SOM_CLK_N
differential pair MIC: +MIC_P -MIC_N
differential pair USB_OTG2: +USB_OTG2_P -USB_OTG2_N
differential pair USB_OTG1: +USB_OTG1_P -USB_OTG1_N

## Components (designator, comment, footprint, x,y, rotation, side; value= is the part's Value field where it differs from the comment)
C1 "100uF" CAPMP3216X120N 56.5,53.4 r270 bottom
C2 "10uF" CAPC1005X55N#1 53.325,53.775 r90 bottom
C3 "1.0uF" CAPC1005X55N#1 54.375,53.775 r90 bottom
C4 "1.0uF" CAPC1005X55L 40.75,37.92 r90 bottom
C5 "2.2UF" CAPC1608X90N 42.2,31.75 r180 bottom
C6 "10uF" CAPC1005X55N#1 38.45,60.9 r270 bottom
C7 "100uF" CAPMP3216X120N 37.525,63.875 r0 bottom
C8 "22µF" CAPC1608X90N 37.625,67.675 r180 bottom
C9 "100nF" CAPC1005X55N#1 37.6,66.15 r180 bottom
C10 "47uF" CAPC2013X145N 56.15,63.3 r270 bottom
C11 "22µF" CAPC1608X90N 54.55,63.3 r270 bottom
C12 "100nF" CAPC1005X55N#1 53.3,63.3 r270 bottom
C13 "100nF" CAPC1005X55N#1 47.2,63.4 r180 bottom
C14 "47pF" CAPC1005X55N#1 47.2,62.2 r180 bottom
C15 "10uF" CAPC2013X135N 60.2,68.3 r90 bottom
C16 "10uF" CAPC2013X135N 58.3,68.3 r90 bottom
C17 "10uF" CAPC2013X135N 56.4,68.3 r90 bottom
C18 "10uF" CAPC2013X135N 54.5,68.3 r90 bottom
C19 "100uF" CAPMP3216X120N 80.4,58.4 r0 bottom
C20 "100uF" CAPMP3216X120N 84.6,63.8 r180 top
C21 "100uF" CAPMP3216X120N 89.975,63.825 r180 top
C22 "100nF" CAPC1005X55N#1 78.75,63.75 r270 top
C23 "100nF" CAPC1005X55N#1 84.025,71.125 r0 bottom
C24 "100nF" CAPC1005X55N#1 89.6,59.6 r0 bottom
C25 "100nF" CAPC1005X55N#1 67.1,59.675 r180 bottom
C26 "100nF" CAPC1005X55N#1 86.25,71.125 r180 bottom
C27 "10uF" CAPC1005X55N#1 97.8,33.875 r180 top
C28 "100nF" CAPC1005X55N#1 97.8,34.8 r180 top
C29 "100nF" CAPC1005X55N#1 26.15,43.975 r270 bottom
C30 "100nF" CAPC1005X55N#1 26.175,48.85 r90 bottom
C31 "100nF" CAPC1005X55N#1 25.55,29.675 r0 top
C32 "100nF" CAPC1005X55N#1 21.65,43.9 r180 top
C33 "100nF" CAPC1005X55N#1 14.959,53.281 r180 bottom
C34 "1.0uF" CAPC1005X55L 30.8,53.1 r180 bottom
C35 "1.0uF" CAPC1005X55L 30.8,52.1 r180 bottom
C36 "1.0uF" CAPC1005X55L 32.9,50.3 r180 bottom
C37 "100uF" CAPC3216X190N 11.8,52.1 r90 top
C38 "100nF" CAPC1005X55N#1 13.725,51.075 r90 top
C39 "100nF" CAPC1005X55N#1 14.175,35 r270 bottom
C40 "100nF" CAPC1005X55N#1 15.5,35 r270 bottom
C41 "1nF" CAPC1005X55N#1 34.9,22.05 r0 bottom
C42 "22pF" CAPC1005X55N#1 31.975,29.275 r90 bottom
C43 "22pF" CAPC1005X55N#1 31.975,31.125 r270 bottom
C44 "100nF" CAPC1005X55N#1 28.55,42.2 r180 bottom
C45 "100nF" CAPC1005X55N#1 14.6,19.107 r0 bottom
C46 "100nF" CAPC1005X55N#1 96.215,44.1 r180 top
C47 "10uF" CAPC1005X55N#1 31.725,33.425 r270 bottom
C48 "100nF" CAPC1005X55N#1 30.7,33.425 r270 bottom
C49 "100nF" CAPC1005X55N#1 26.14,24.167 r0 bottom
C50 "1.0uF" CAPC1005X55N#1 26.14,25.192 r0 bottom
C51 "100nF" CAPC1005X55N#1 19.9,30.3 r270 bottom
C52 "1.0uF" CAPC1005X55N#1 20.85,29.875 r270 bottom
C53 "1.0uF" CAPC1005X55N#1 31.25,25.6 r180 bottom
C54 "10uF" CAPC1005X55N#1 27.3,38.275 r0 bottom
C55 "100nF" CAPC1005X55N#1 27.2,37.35 r0 bottom
C56 "100nF" CAPC1005X55N#1 31.25,27.625 r180 bottom
C57 "100nF" CAPC1005X55N#1 24.625,24.675 r90 bottom
C58 "0.22uF" CAPC1005X55N#1 28.625,25.925 r90 bottom
C59 "0.22uF" CAPC1005X55N#1 26.125,34.6 r0 bottom
C60 "22pF" CAPC1005X55N#1 30.2,36.1 r180 top
C61 "22pF" CAPC1005X55N#1 27.9,36.1 r0 top
C62 "100nF" CAPC1005X55N#1 27.3,39.425 r0 bottom
C63 "100nF" CAPC1005X55N#1 31.2,19.2 r0 top
C64 "100nF" CAPC1005X55N#1 98.215,44.1 r0 top
C65 "10uF" CAPC1005X55N#1 26.4,37 r90 top
C66 "100nF" CAPC1005X55N#1 25.45,37 r90 top
C67 "100nF" CAPC1005X55N#1 34.925,42.5 r270 top
C68 "1.0uF" CAPC1005X55N#1 34,42.5 r270 top
C69 "100nF" CAPC1005X55N#1 29.375,48.1 r270 bottom
C70 "1.0uF" CAPC1005X55N#1 29.375,48.1 r270 top
C71 "1.0uF" CAPC1005X55N#1 32.2,38.425 r180 top
C72 "10uF" CAPC1005X55N#1 22.5,41.4 r270 top
C73 "100nF" CAPC1005X55N#1 21.525,41.4 r270 top
C74 "100nF" CAPC1005X55N#1 32.2,37.275 r180 top
C75 "100nF" CAPC1005X55N#1 34.1,43.875 r180 top
C76 "0.22uF" CAPC1005X55N#1 33.625,39.5 r90 top
C77 "0.22uF" CAPC1005X55N#1 24.95,41.875 r270 top
C78 "100nF" CAPC1005X55N#1 74.95,63.8 r90 top
C79 "1.0uF" CAPC1005X55L 33.075,49.325 r180 bottom
C80 "100nF" CAPC1005X55N#1 20.125,64.875 r180 bottom
C81 "33pF" CAPC1005X55N#1 23.919,57.191 r90 top
C82 "33pF" CAPC1005X55N#1 23.925,55.3 r270 top
C83 "1.0uF" CAPC1005X55N#1 27.05,59.05 r90 bottom
C84 "1.0uF" CAPC1005X55N#1 55.375,19.925 r0 bottom
C85 "10uF" CAPC1005X55N#1 47.95,18.7 r270 bottom
C86 "100nF" CAPC1005X55N#1 49.025,18.7 r270 bottom
C87 "10uF" CAPC1005X55N#1 47.95,18.7 r270 top
C88 "100nF" CAPC1005X55N#1 49.025,18.7 r270 top
C89 "1nF" CAPC1005X55N#1 39.225,60.65 r270 top
C90 "10uF" CAPC1005X55N#1 24.6,53.125 r90 top
C91 "100nF" CAPC1005X55N#1 24.6,52.325 r0 bottom
C92 "100nF" CAPC1005X55N#1 33.6,54.225 r180 top
C93 "100nF" CAPC1005X55N#1 33.6,57.25 r180 top
C94 "100nF" CAPC1005X55N#1 23.919,59.091 r270 top
C95 "100nF" CAPC1005X55N#1 29.425,61 r180 bottom
C96 "100nF" CAPC1005X55N#1 33.6,56.275 r180 top
C97 "100nF" CAPC1005X55N#1 19.8,53.5 r0 top
C98 "100nF" CAPC1005X55N#1 70.475,11.075 r90 bottom
C99 "100nF" CAPC1005X55N#1 70.4,16.3 r0 top
C100 "100nF" CAPC1005X55N#1 76.15,15.525 r180 top
C101 "2.2µF" CAPC1005X55L 76.15,16.65 r180 top
C102 "2.2µF" CAPC1005X55L 77.26,18.14 r90 top
C103 "10uF" CAPC1005X55N#1 71.7,11.075 r270 bottom
C104 "10uF" CAPC1005X55N#1 71.13,20.55 r270 bottom
C105 "100nF" CAPC1005X55N#1 72.08,20.55 r270 bottom
C106 "10uF" CAPC1005X55N#1 72.05,16.175 r90 bottom
C107 "100nF" CAPC1005X55N#1 71.025,16.175 r90 bottom
C108 "100nF" CAPC1005X55N#1 69.95,16.175 r90 bottom
C109 "1.0uF" CAPC1005X55L 36.425,55.675 r0 bottom
C110 "1.0uF" CAPC1005X55L 34.25,53 r90 bottom
C111 "1.0uF" CAPC1005X55L 35.15,53 r90 bottom
C112 "10pF" CAPC1005X55N#1 30.8,54 r180 bottom
C113 "10pF" CAPC1005X55N#1 30.8,51.2 r180 bottom
C114 "10pF" CAPC1005X55N#1 32.9,51.2 r0 bottom
C115 "10pF" CAPC1005X55N#1 33.05,48.075 r180 bottom
C116 "10pF" CAPC1005X55N#1 30.8,48 r180 bottom
C117 "10pF" CAPC1005X55N#1 31.2,44.8 r0 bottom
C118 "100nF" CAPC1005X55N#1 44.3,48.1 r0 bottom
C119 "100nF" CAPC1005X55N#1 42.2,52.45 r90 bottom
C120 "10uF" CAPC1005X55N#1 38.5,55.75 r0 bottom
C121 "1.0uF" CAPC1005X55N#1 40,55.1 r90 bottom
C122 "1.0uF" CAPC1005X55N#1 38.5,54.75 r180 bottom
C123 "1.0uF" CAPC1005X55N#1 35.625,41.875 r180 bottom
C124 "10uF" CAPC1005X55N#1 41.125,41.7 r180 bottom
C125 "1.0uF" CAPC1005X55N#1 39.3,41.7 r180 bottom
C126 "1.0uF" CAPC1005X55N#1 39.3,42.625 r180 bottom
C127 "1.0uF" CAPC1005X55N#1 35.625,42.925 r0 bottom
C128 "1.0uF" CAPC1005X55N#1 33.192,46.15 r0 bottom
C129 "1.0uF" CAPC1005X55N#1 33.192,45.225 r0 bottom
C130 "2.2µF" CAPC1005X55N#1 37,52.975 r90 bottom
C131 "1.0uF" CAPC1005X55N#1 38,52.95 r270 bottom
C132 "1.0uF" CAPC1005X55N#1 85.725,20.95 r90 bottom
C133 "1nF" CAPC1005X55N#1 41.175,60.1 r180 bottom
C134 "1nF" CAPC1005X55N#1 36.4,36.3 r0 bottom
C135 "1uF" CAPC1608X90N 47.6,65.3 r270 bottom
C136 "15nF" CAPC1005X55N#1 49.35,59.5 r90 bottom
C137 "220nF" CAPC0603X33N 82.7,49.8 r270 bottom
C138 "220nF" CAPC0603X33N 81.55,49.8 r270 bottom
C139 "100nF" CAPC1005X55N#1 70.275,68.525 r90 top
C140 "100nF" CAPC1005X55N#1 71.3,68.525 r90 top
C142 "15nF" CAPC1005X55N#1 79.7,19.9 r180 bottom
C143 "2.2UF" CAPC1608X90N 42.9,39.6 r90 bottom
C145 "100nF" CAPC1005X55N#1 25.55,34.55 r180 top
C146 "100nF" CAPC1005X55N#1 18.8,40.325 r270 bottom
C147 "1.0uF" CAPC1005X55N#1 46,36 r90 bottom
C148 "100nF" CAPC1005X55N#1 44.8,32.6 r90 top
C149 "10uF" CAPC1005X55N#1 42.9,32.6 r90 top
C150 "100nF" CAPC1005X55N#1 66.825,13.15 r270 bottom
C151 "100nF" CAPC1005X55N#1 67.85,13.15 r270 bottom
C152 "100nF" CAPC1005X55N#1 74.3,12.8 r270 top
C153 "100nF" CAPC1005X55N#1 73.275,12.8 r270 top
C154 "10uF" CAPC1005X55N#2 28,62.95 r180 bottom
C155 "100uF" CAPMP3216X120N 31.135,64 r270 bottom
C156 "22µF" CAPC1608X90N 28.025,65.7 r0 bottom
C157 "100nF" CAPC1005X55N#2 27.975,67.225 r0 bottom
C158 "10uF" CAPC1005X55N#2 23.425,62.95 r180 bottom
C159 "100uF" CAPMP3216X120N 25.7,63.475 r270 bottom
C160 "22µF" CAPC1608X90N 23.4,65.7 r0 bottom
C161 "100nF" CAPC1005X55N#2 23.325,67.35 r0 bottom
C162 "4.7uF" CAPC1005X55N#2 44.55,47.9 r270 top
CAD1 "TC2050-IDC-NL" TC_TC2050-IDC-NL#1 38.635,23.87 r270 bottom
CAD2 "TC2050-IDC-NL" TC_TC2050-IDC-NL#2 14.765,59.43 r270 bottom locked
D1 "IP4292CZ10" SON50P250X100X50-10N 70.9,10.85 r90 top
D2 "ESD9B5.0ST5G" SODFL1006X43N12 58.325,6.6 r270 bottom
D3 "MMSZ5231BT1G" SOD3716X135N 85.65,16.475 r90 bottom
D4 "BAT54CWT1G" SOT65P210X100-3AN 39.569,36.159 r180 bottom
D5 "597-3301-507F" LEDM3020X130N 33.3,28.9 r90 top
D6 "ESD9B3.3ST5G" SODFL1006X43AN12 96,53.875 r0 top
D7 "ESD9B3.3ST5G" SODFL1006X43AN12 97.925,53.9 r180 top
D8 "1N5819HW-7-F" SOD3716X135N 73.38,17.85 r90 bottom
D9 "IP4292CZ10" SON50P250X100X50-10N 68.1,10.8 r270 top
D10 "IP4292CZ10" SON50P250X100X50-10N 73.95,10.875 r90 top
D11 "597-3301-507F" LEDM3020X130N 30.25,28.9 r90 top
D12 "597-3401-507F" LEDM3020X130N 27.75,28.9 r90 top
D13 "DB2J31400L" SODFL2513X80N 44.325,50.9 r270 top
D14 "SMA6J5.0A" DIOM5127X229AN 76.75,19.805 r90 bottom
FIDUCIAL1 "40mil FID" fiducial_40mil_round 98.5,8.9 r90 bottom
FIDUCIAL2 "40mil FID" fiducial_40mil_round 28.675,70.1 r90 bottom
FIDUCIAL3 "40mil FID" fiducial_40mil_round 94.4,65.4 r90 bottom
FIDUCIAL4 "40mil FID" fiducial_40mil_round 1.175,65.475 r90 top
FIDUCIAL5 "40mil FID" fiducial_40mil_round 6.2,5.4 r90 top
FIDUCIAL6 "40mil FID" fiducial_40mil_round 312.5,2.5 r90 top
FIDUCIAL7 "40mil FID" fiducial_40mil_round 49.15,62.675 r270 top
FIDUCIAL8 "40mil FID" fiducial_40mil_round 98.5,8.9 r90 top
FIDUCIAL9 "40mil FID" fiducial_40mil_round 94.4,65.4 r90 top
FIDUCIAL10 "40mil FID" fiducial_40mil_round 1.175,65.475 r90 bottom
FIDUCIAL11 "40mil FID" fiducial_40mil_round 18.8,19.45 r90 bottom
FIDUCIAL12 "40mil FID" fiducial_40mil_round 312.5,2.5 r90 bottom
FIL1 "NFM21PC105B1A3D" FIL_NFM21P 83.95,16.6 r180 top
H1 "125mil" MH_185_125_NP -7.5,-4 r0 top locked
H2 "125mil" MH_185_125_NP -7.5,72 r0 top locked
H3 "125mil" MH_185_125_NP 312.5,72 r0 top
H4 "125mil" MH_185_125_NP 312.5,-4 r0 top
J2 "1x2P" MOLEX_53047-0210 2.2,7.85 r90 top
J3 "1x2P" MOLEX_53047-0210 5.7,7.85 r90 top
J4 "CSCD443CCS011B00G" conn_CSCD443CCS011B00G 90,11.904 r90 top locked
J5 "640456-2" TE_640456-2 97.225,14.225 r0 top
J6 "1x2P" MOLEX_53047-0210 9.2,7.85 r90 top
J7 "PCIe Minicard" FOXCONN_AS0B221-S68Q-7H 65.6,65.4 r0 bottom locked
J8 "78727-0001" MOLEX_78727-0001 98.67,45.38 r0 bottom locked
J9 "FTSH-105-01-F-DV" SAMTEC_FTSH-105-01-F-DV 14.8,59.4 r0 top
J10 "500873-0806" MOLEX_500873-0806 94.75,28.4 r90 bottom
J11 "1x4" MOLEX_53047-0410 98.15,57.475 r180 top
J12 "RJ45" XMULTIPLE_XMG-J1B211 14.501,16.005 r0 top locked
J13 "RJ45" XMULTIPLE_XMG-J1B211 32.751,16.005 r0 top locked
J14 "DF14A-20P-1.25H(25)" HIROSE_DF14A-20P-1.25H 21.375,67.65 r0 top locked
J15 "SFW15S-2STE1LF" FCI_SFW15S-2STE1LF 82.45,67.925 r0 top locked
J16 "DF14A-20P-1.25H(25)" HIROSE_DF14A-20P-1.25H 52.175,67.65 r0 top
J17 "1x20P" omron_xf2m-2015-1a 14,68.6 r0 bottom locked
J18 "KUSBX-AS2N" KYCON_KUSBX-AS2N_Flex 52.301,13.485 r0 top locked
J19 "USB_C" MOLEX_201267-0005 70.1,3.975 r0 top
J20 "802-10-040-001000" "MILLMAX_ 802-10-040-62-001000" 1.425,60.325 r0 top
J21 "SJ1-3533NG" CUI_SJ1-3533N 80.75,1.225 r90 top
J22 "SMM-110-02-F-S-P-TR" SAMTEC_SMM-110-02-F-S 16.992,43.875 r270 top locked
J23 "SMM-110-02-F-S-P-TR" SAMTEC_SMM-110-02-F-S 38.992,43.875 r270 top locked
J27 "802-10-040-001000" "MILLMAX_ 802-10-040-62-001000" 6.575,60.325 r0 top
J28 "KMMX-ABSMT5SG-30TR" KYCON_KMMX-ABSMT5 56,1.7 r180 bottom
L1 "1.5UH" INDM_SRP4020TA 51.2,67.575 r90 bottom
L2 "120" INDC1005X60N 26.6,22.575 r90 bottom
L3 "4.7uH" INDC2520X100L60N 29.8,36.35 r90 bottom
L4 "120" INDC1005X60N 27.225,36 r0 bottom
L5 "120" INDC1005X60N 34.9,40.5 r90 top
L6 "4.7uH" INDC2520X100L60N 22.95,38.75 r180 top
L7 "120" INDC1005X60N 23.5,41.4 r270 top
L8 "220" INDC2013X110N 24.275,69.7 r180 bottom
L9 "744231121" FIL_DLW21H 54.975,17.55 r270 bottom
L10 "744231121" FIL_DLW21H 56.625,17.55 r270 bottom
L11 "744231121" FIL_DLW21H 31.475,51.225 r180 top
L12 "744231121" FIL_DLW21H 13.925,25.577 r270 bottom
L13 "220" INDC2013X110N 61,18.5 r180 bottom
L14 "220" INDC2013X110N 60.6,18.525 r180 top
L15 "220" INDC2013X110N 33.1,62.2 r270 top
L16 "1.8K" INDC1005X60N 33.7,55.325 r270 bottom
L17 "1.8K" INDC1005X60N 34.9,55.325 r270 bottom
L18 "1.8K" INDC1005X60N 28.825,53.95 r0 bottom
L19 "1.8K" INDC1005X60N 28.825,52.675 r0 bottom
L20 "1.8K" INDC1005X60N 30.825,50.1 r0 bottom
L21 "1.8K" INDC1005X60N 30.8,49.025 r0 bottom
L22 "220" INDC2013X110N 19.875,58.275 r90 bottom
L23 "220" INDC2013X110N 19.875,59.975 r270 bottom
L24 "DLP11SN900" FIL_DLP11S 31.075,62.625 r90 top
L25 "DLP11SN900" FIL_DLP11S 27.325,62.625 r90 top
L26 "DLP11SN900" FIL_DLP11S 23.575,62.625 r90 top
L27 "DLP11SN900" FIL_DLP11S 20.15,62.775 r90 top
L28 "DLP11SN900" FIL_DLP11S 17.8,63.1 r180 top
L29 "220" INDC2013X110N 51.5,18.5 r180 bottom
L30 "220" INDC2013X110N 51.5,18.5 r180 top
L31 "DLP11SN900" FIL_DLP11S 62.2,62.8 r90 top
L32 "DLP11SN900" FIL_DLP11S 58.5,62.8 r90 top
L33 "DLP11SN900" FIL_DLP11S 54.7,62.8 r90 top
L34 "DLP11SN900" FIL_DLP11S 51,62.8 r90 top
L35 "DLP11SN900" FIL_DLP11S 47.2,62.8 r90 top
L36 "220" INDC2013X110N 41,61.4 r90 top
L37 "220" INDC2013X110N 48.025,22.3 r180 bottom
L38 "744231121" FIL_DLW21H 56.975,6.775 r270 bottom
L39 "220" INDC2013X110N 54.5,6.55 r0 bottom
NT1 "NET TIE" NET_TIE_4mil 34.325,47 r180 bottom net-tie
Q1 "2N7002T" SOTFL50P160X80_GSD-3N 82.9,20.2 r270 bottom
Q2 "2N7002T" SOTFL50P160X80_GSD-3N 33,21.2 r90 bottom
Q3 "2N7002T" SOTFL50P160X80_GSD-3N 38.55,62.825 r180 top
Q4 "2N7002T" SOTFL50P160X80_GSD-3N 72,22.6 r270 bottom
Q5 "2N7002T" SOTFL50P160X80_GSD-3N 37.25,31.3 r180 bottom
Q6 "NTR4003NT1G" SOT95P240X110_GSD-3N 42.1,66.1 r0 bottom
Q7 "MMBT3906LT1G" SOT95P240X110-3N 83,16.5 r90 bottom
Q8 "2N7002T" SOTFL50P160X80_GSD-3N 35.75,28.9 r0 top
Q9 "NTR4003NT1G" SOT95P240X110_GSD-3N 36.5,34.1 r90 bottom
Q10 "NTR4003NT1G" SOT95P240X110_GSD-3N 41.8,62.4 r270 bottom
Q11 "NTR4003NT1G" SOT95P240X110_GSD-3N 34.075,25.625 r90 bottom
Q12 "NTR4003NT1G" SOT95P240X110_GSD-3N 35.6,61.5 r180 top
Q13 "2N7002T" SOTFL50P160X80_GSD-3N 33.66,32 r90 top
Q14 "2N7002T" SOTFL50P160X80_GSD-3N 33.3,34.3 r90 top
R1 "0" RESC2013X70N 51.075,53.825 r180 bottom
R2 "0" RESC1005X40N#1 30.075,67.225 r180 bottom
R3 "0" RESC1005X40N#1 25.475,67.35 r180 bottom
R4 "0" RESC1005X40N#1 69.425,58.9 r180 bottom
R5 "0" RESC1005X40N#1 81.1,40.5 r0 bottom
R6 "0" RESC1005X40N#1 81.1,41.6 r0 bottom
R7 "0" RESC1005X40N#1 81.1,39.4 r0 bottom
R8 "0" RESC1005X40N#1 55.45,37.875 r180 bottom
R9 "0" RESC1005X40N#1 56.6,32.4 r180 bottom
R10 "10.0K" RESC1005X40N#1 81.55,22.3 r90 bottom
R11 "0" RESC1005X40N#1 18.1,26.56 r90 top
R12 "10.0K" RESC1005X40N#1 81.625,33.55 r90 bottom
R13 "0" RESC1005X40N#1 14.12,26.3 r0 top
R14 "0" RESC1005X40N#1 42.5,19.7 r180 bottom
R15 "51K" RESC1005X40N#1 16.02,26.3 r0 top
R16 "10.0K" RESC1005X40N#1 20.5,39.55 r270 bottom
R17 "100K" RESC1005X40N#1 21.75,21.5 r180 bottom
R18 "0" RESC1005X40N#1 8.5,4.8 r0 top
R19 "270" RESC2013X70N 81.8,13.6 r180 bottom
R20 "10.0K" RESC1005X40N#1 84,13.7 r90 bottom
R21 "10.0K" RESC1005X40N#1 81.4,18.5 r270 bottom
R22 "0.0" RESC2013X70N 79.05,15.55 r180 bottom
R23 "1.0K" RESC1005X40N#1 80.6,20.9 r0 bottom
R24 "470K" RESC1005X40N#1 85.175,19.45 r180 bottom
R25 "2.2M" RESC1005X40N#1 84.65,20.95 r90 bottom
R26 "12K" RESC1609X55N 42.2,33.25 r180 bottom
R27 "20K" RESC1609X55N 44.75,32.55 r90 bottom
R28 "0" RESC1005X40N#1 38.9,33.4 r270 bottom
R29 "0" RESC1005X40N#1 42.5,21.1 r180 bottom
R30 "49.9" RESC1005X40N#1 92.825,45.2 r180 top
R31 "0.0" RESC2013X70N 40.35,39.92 r0 bottom
R32 "4.7K" RESC1005X40N#1 41.7,20.3 r270 top
R33 "100K" RESC1005X40N#1 38.5,25.7 r180 top
R34 "0" RESC1005X40N#1 31.2,20.2 r180 top
R35 "4.7K" RESC1005X40N#1 29.7,22.3 r270 top
R36 "4.7K" RESC1005X40N#1 43.22,29.275 r0 top
R37 "100K" RESC1005X40N#1 44.18,29.275 r180 top
R38 "4.7K" RESC1005X40N#1 43.22,30.4 r0 top
R39 "100K" RESC1005X40N#1 44.18,30.4 r180 top
R40 "100K" RESC1005X40N#1 34.35,61.2 r270 bottom
R41 "0" RESC1609X55N 34.975,65.95 r180 bottom
R42 "220" RESC1005X40N#1 33.3,26.3 r180 top
R43 "470K" RESC1005X40N#1 52.3,62.65 r90 bottom
R44 "470K" RESC1005X40N#1 52.3,60.7 r90 bottom
R45 "0" RESC1005X40N#1 44.4,63.975 r270 bottom
R46 "100K" RESC1005X40N#1 50.4,59.5 r90 bottom
R47 "100K" RESC1005X40N#1 44.4,62.1 r270 bottom
R48 "2R" RESC1609X55N 45.6,64.3 r90 bottom
R49 "53.6k" RESC1609X55N 46.1,60.2 r270 bottom
R50 "12K" RESC1609X55N 47.6,60.2 r90 bottom
R51 "10.0K" RESC1005X40N#1 56.675,34.8 r0 bottom
R52 "10.0K" RESC1005X40N#1 68.4,67.2 r270 top
R53 "22.1K" RESC1005X40N#1 94.7,34.4 r90 top
R54 "100K" RESC1005X40N#1 82.75,28.45 r90 bottom
R55 "10.0K" RESC1005X40N#1 94.7,36.25 r270 top
R56 "0" RESC1005X40N#1 96.1,34.52 r270 top
R57 "0" RESC1005X40N#1 96.1,35.48 r90 top
R58 "100" RESC1005X40N#1 77.05,58.7 r0 bottom
R59 "1.0K" RESC1005X40N#1 19.74,26.56 r90 top
R60 "120" RESC1005X40N#1 16.5,30.3 r270 top
R61 "1.0K" RESC1005X40N#1 12.459,46.681 r270 bottom
R62 "120" RESC1005X40N#1 14.375,40.8 r0 bottom
R63 "120" RESC1005X40N#1 12.175,48.775 r180 top
R64 "100" RESC1005X40N#1 87.1,21.2 r90 bottom
R65 "0" RESC1005X40N#1 13.075,34.95 r270 bottom
R66 "0" RESC1005X40N#1 12.725,33.5 r0 bottom
R67 "0" RESC1005X40N#1 16.7,36.275 r270 bottom
R68 "0" RESC1005X40N#1 16.65,31.775 r90 bottom
R69 "100K" RESC1005X40N#1 31.3,20.6 r90 bottom
R70 "10.0K" RESC1005X40N#1 32.3,22.7 r0 bottom
R71 "0" RESC1609X55N 29.4,20.95 r180 bottom
R72 "1.0K" RESC1005X40N#1 33.365,34.992 r0 bottom
R73 "1.0K" RESC1005X40N#1 33.365,35.992 r0 bottom
R74 "10.0K" RESC1005X40N#1 33.64,33.592 r0 bottom
R75 "10.0K" RESC1005X40N#1 24.54,35.192 r90 bottom
R76 "0" RESC1005X40N#1 13.525,42.35 r90 top
R77 "0" RESC1005X40N#1 12,42.35 r90 top
R78 "0" RESC1005X40N#1 11.75,21.6 r180 top
R79 "0" RESC1005X40N#1 11.75,22.85 r180 top
R80 "10.0K" RESC1005X40N#1 24.2,39 r270 bottom
R81 "4.7K" RESC1005X40N#1 25.675,36.325 r270 bottom
R82 "2.37K" RESC1005X40N#1 31.275,26.625 r180 bottom
R83 "150" RESC1005X40N#1 28.9,19.025 r90 bottom
R84 "150" RESC1005X40N#1 10.8,4.8 r180 top
R85 "0" RESC3225X60N 8.9,2.7 r0 top
R86 "10.0K" RESC1005X40N#1 20.915,36.272 r90 bottom
R87 "10.0K" RESC1005X40N#1 20.915,35.312 r90 bottom
R88 "10.0K" RESC1005X40N#1 19.89,36.272 r90 bottom
R89 "10.0K" RESC1005X40N#1 19.89,35.312 r90 bottom
R90 "10.0K" RESC1005X40N#1 21.76,24.475 r180 bottom
R91 "10.0K" RESC1005X40N#1 22.72,24.475 r180 bottom
R92 "10.0K" RESC1005X40N#1 21.94,36.272 r90 bottom
R93 "10.0K" RESC1005X40N#1 21.94,35.312 r90 bottom
R94 "10.0K" RESC1005X40N#1 18.865,36.272 r90 bottom
R95 "10.0K" RESC1005X40N#1 18.865,35.312 r90 bottom
R96 "10.0K" RESC1005X40N#1 22.965,36.272 r90 bottom
R97 "10.0K" RESC1005X40N#1 22.965,35.312 r90 bottom
R98 "10.0K" RESC1005X40N#1 17.84,36.272 r90 bottom
R99 "10.0K" RESC1005X40N#1 17.84,35.312 r90 bottom
R100 "10.0K" RESC1005X40N#1 21.76,25.475 r180 bottom
R101 "10.0K" RESC1005X40N#1 22.72,25.475 r180 bottom
R102 "12K" RESC1609X55N 30.8,30.3 r90 bottom
R103 "12K" RESC1609X55N 28.9,37.225 r180 top
R104 "1.0K" RESC1005X40N#1 24.075,35.7 r270 top
R105 "1.0K" RESC1005X40N#1 23.075,35.7 r270 top
R106 "10.0K" RESC1005X40N#1 29.35,38.925 r0 bottom
R107 "10.0K" RESC1005X40N#1 24.45,44 r180 top
R108 "100K" RESC1005X40N#1 36.12,34.28 r90 top
R109 "100K" RESC1005X40N#1 36.1,32 r90 top
R110 "22" RESC1005X40N#1 94.825,45.2 r180 top
R111 "22" RESC1005X40N#1 94.825,46.225 r180 top
R112 "49.9" RESC1005X40N#1 92.8,48.275 r0 top
R113 "4.7K" RESC1005X40N#1 23.05,41.05 r180 bottom
R114 "2.37K" RESC1005X40N#1 34.225,37.85 r180 top
R115 "150" RESC1005X40N#1 46.5,19.4 r90 bottom
R116 "150" RESC1005X40N#1 30.1,19.025 r90 bottom
R117 "49.9" RESC1005X40N#1 92.825,46.225 r180 top
R118 "10.0K" RESC1005X40N#1 22.745,47.4 r180 top
R119 "10.0K" RESC1005X40N#1 23.705,47.4 r180 top
R120 "10.0K" RESC1005X40N#1 22.745,48.4 r180 top
R121 "10.0K" RESC1005X40N#1 23.705,48.4 r180 top
R122 "10.0K" RESC1005X40N#1 35.4,46.855 r90 top
R123 "10.0K" RESC1005X40N#1 35.4,45.895 r90 top
R124 "10.0K" RESC1005X40N#1 22.72,45.975 r180 top
R125 "10.0K" RESC1005X40N#1 23.68,45.975 r180 top
R126 "10.0K" RESC1005X40N#1 22.745,49.675 r180 top
R127 "10.0K" RESC1005X40N#1 23.705,49.675 r180 top
R128 "10.0K" RESC1005X40N#1 22.72,45 r180 top
R129 "10.0K" RESC1005X40N#1 23.68,45 r180 top
R130 "10.0K" RESC1005X40N#1 22.745,50.625 r180 top
R131 "10.0K" RESC1005X40N#1 23.705,50.625 r180 top
R132 "10.0K" RESC1005X40N#1 34.25,46.88 r90 top
R133 "10.0K" RESC1005X40N#1 34.25,45.92 r90 top
R134 "10.0K" RESC1005X40N#1 10.2,63.4 r180 top
R135 "1M_1%" RESC1005X40N#1 24.869,56.191 r270 top
R136 "47K" RESC1005X40N#1 25.425,61.925 r0 top
R137 "10.0K" RESC1005X40N#1 26.65,60.85 r180 top
R138 "47K" RESC1005X40N#1 30.025,59.05 r90 bottom
R139 "47K" RESC1005X40N#1 28.95,59.05 r90 bottom
R140 "47K" RESC1005X40N#1 28,59.05 r90 bottom
R141 "12.1k" RESC1005X40N#1 23.5,53.175 r90 top
R142 "10.0K" RESC1005X40N#1 54.65,29.65 r90 bottom
R143 "10.0K" RESC1005X40N#1 55.9,29.65 r90 bottom
R144 "100K" RESC1005X40N#1 37.9,64.7 r0 top
R145 "10.0K" RESC1005X40N#1 37.725,60.175 r0 top
R146 "0" RESC1609X55N 35.809,58.069 r270 top
R147 "10.0K" RESC1005X40N#1 70.4,18.275 r0 top
R148 "10.0K" RESC1005X40N#1 70.4,17.25 r0 top
R149 "47K" RESC1005X40N#1 69.25,19.5 r90 bottom
R150 "52.3k" RESC1005X40N#1 68.75,21.375 r0 bottom
R151 "1.0K" RESC1005X40N#1 70.205,20.55 r270 bottom
R152 "22.1K" RESC1005X40N#1 70.2,22.425 r270 bottom
R153 "100K" RESC1005X40N#1 73.7,22.55 r90 bottom
R154 "10.0K" RESC1005X40N#1 43.2,52.78 r270 bottom
R155 "0" RESC1005X40N#1 44,50.225 r180 bottom
R156 "0" RESC1005X40N#1 44,49.3 r180 bottom
R157 "0" RESC1005X40N#1 41.2,52.775 r270 bottom
R158 "0" RESC1005X40N#1 44,51.15 r180 bottom
R159 "2.2K" RESC1005X40N#1 36.525,54.575 r180 bottom
R160 "100" RESC1005X40N#1 34.875,23.25 r0 bottom
R161 "100" RESC1005X40N#1 34,59.6 r270 top
R162 "2.2M" RESC1005X40N#1 88.1,21.225 r90 bottom
R163 "10.0K" RESC1005X40N#1 23.2,46.45 r180 bottom
R164 "0" RESC1005X40N#1 30.75,46.975 r180 bottom
R165 "0" RESC1005X40N#1 30.55,45.95 r180 bottom
R166 "100" RESC1005X40N#1 38.5,38 r90 bottom
R167 "100" RESC1005X40N#1 39.6,60.9 r270 bottom
R168 "100K" RESC1005X40N#1 38.9,31.2 r90 bottom
R169 "10.0K" RESC1005X40N#1 33.7,38.5 r270 bottom
R170 "0" RESC1609X55N 36.1,40.675 r0 bottom
R171 "2.2K" RESC1005X40N#1 82.05,25.9 r90 bottom
R172 "2.2K" RESC1005X40N#1 83.225,25.9 r90 bottom
R173 "0" RESC1005X40N#1 74.16,19.68 r180 top
R174 "0" RESC1005X40N#1 76.46,19.68 r180 top
R175 "0" RESC1005X40N#1 39.025,52.95 r270 bottom
R176 "0" RESC1005X40N#1 40,52.95 r270 bottom
R177 "0" RESC1005X40N#1 80.6,63.1 r270 top
R178 "0" RESC1005X40N#1 81.7,63.15 r270 top
R179 "2.2K" RESC1005X40N#1 11.3,64.05 r270 bottom
R180 "2.2K" RESC1005X40N#1 13.5,64.925 r0 bottom
R181 "2.2K" RESC1005X40N#1 42.8,62.5 r270 top
R182 "2.2K" RESC1005X40N#1 44.1,62.5 r270 top
R183 "2.2K" RESC1005X40N#1 76.35,63.75 r270 top
R184 "2.2K" RESC1005X40N#1 77.65,63.8 r270 top
R185 "0" RESC1005X40N#1 17.625,64.35 r90 bottom
R186 "0" RESC1005X40N#1 18.624,64.35 r90 bottom
R187 "0" RESC1005X40N#1 11.7,47.35 r270 top
R188 "0" RESC1005X40N#1 11.7,45 r270 top
R189 "0" RESC1005X40N#1 20.3,48.8 r270 top
R190 "0" RESC1005X40N#1 20.6,45.3 r270 top
R191 "0" RESC1005X40N#1 28.525,50.55 r180 top
R192 "0" RESC1005X40N#1 28.525,51.5 r180 top
R193 "10.0K" RESC1005X40N#1 35.9,58.1 r270 bottom
R194 "100K" RESC1005X40N#1 41.8,68.65 r180 bottom
R195 "49.9" RESC1005X40N#1 92.825,47.25 r0 top
R196 "0" RESC1005X40N#1 41.9,40.9 r0 top
R197 "0" RESC1005X40N#1 43.5,34.9 r0 top
R198 "10.0K" RESC1005X40N#1 43.5,45.275 r180 top
R199 "0" RESC1609X55N 34.3,58.175 r270 bottom
R203 "120" RESC1005X40N#1 31.55,25.725 r270 top
R204 "120" RESC1005X40N#1 30.525,25.725 r270 top
R205 "0" RESC1005X40N#1 53,51.3 r0 bottom
R213 "0" RESC1005X40N#1 13.155,26.3 r180 top
R214 "0.0" RESC2013X70N 65.3,11.1 r90 top
R215 "10.0K" RESC1005X40N#1 41,63.5 r180 top
R216 "100K" RESC1005X40N#1 35.73,27.2 r0 top
R217 "49.9" RESC1005X40N#1 71.772,70 r180 top
R218 "49.9" RESC1005X40N#1 69.872,70 r0 top
R219 "0" RESC1609X55N 50.15,51.55 r270 bottom
R220 "0" RESC1609X55N 52.24,55.5 r0 bottom
R221 "0" RESC1005X40N#1 52.9,46.25 r90 bottom
R222 "0" RESC1005X40N#1 83.268,53.85 r180 bottom
R223 "0" RESC1005X40N#1 83.255,54.9 r180 bottom
R224 "0" RESC1005X40N#1 82.9,47.75 r270 bottom
R225 "0" RESC1005X40N#1 81.7,47.75 r270 bottom
R226 "0" RESC1005X40N#1 80.925,52.5 r270 bottom
R227 "0" RESC1005X40N#1 82.05,52.5 r270 bottom
R228 "0" RESC1005X40N#1 28.525,50.55 r180 bottom
R229 "0" RESC1005X40N#1 28.525,51.5 r180 bottom
R230 "0" RESC1005X40N#1 73.48,58.3 r0 bottom
R231 "0" RESC1005X40N#1 74.44,58.3 r0 bottom
R232 "0" RESC1005X40N#1 82.7,22.3 r90 bottom
R233 "0" RESC1005X40N#1 16.775,19.125 r180 bottom
R234 "0" RESC1005X40N#1 75.9,18.12 r270 top
R235 "10.0K" RESC1005X40N#1 48.275,41.425 r180 bottom
R236 "22" RESC1005X40N#1 94.825,48.275 r180 top
R237 "22" RESC1005X40N#1 94.825,47.25 r180 top
R238 "0" RESC1005X40N#1 90.605,54.25 r270 bottom
R239 "0" RESC1005X40N#1 91.525,54.25 r270 bottom
R240 "0" RESC1005X40N#1 25.7,56.96 r270 bottom
R241 "0" RESC1005X40N#1 24.1,56.96 r270 bottom
R242 "0" RESC1005X40N#1 60.975,21.2 r0 bottom
R243 "0" RESC1005X40N#1 60.975,20.175 r0 bottom
R244 "10.0K" RESC1005X40N#1 29.325,40.05 r180 bottom
R245 "0" RESC1005X40N#1 25.075,32.075 r270 top
R246 "0" RESC1005X40N#1 25.55,30.675 r180 top
R247 "0" RESC1005X40N#1 16.2,32.175 r180 top
R248 "0" RESC1005X40N#1 17.85,40.325 r90 bottom
R249 "0" RESC1005X40N#1 21.125,44.175 r90 bottom
R250 "0" RESC1005X40N#1 12.45,42.35 r270 bottom
R251 "10.0K" RESC1005X40N#1 19.4,58.8 r90 top
R252 "0" RESC1005X40N#1 19.4,60.675 r90 top
R253 "10.0K" RESC1005X40N#1 21.825,60.925 r0 bottom
R254 "0" RESC1005X40N#1 22.6,59.75 r270 top
R255 "0.0" RESC2013X70N 90.45,21.25 r0 bottom
R256 "0" RESC1005X40N#1 51.575,56.7 r180 bottom
R257 "0" RESC1005X40N#1 60.325,61.25 r180 bottom
R258 "47k" RESC1005X40N#1 43,50.85 r270 top
R259 "100K" RESC1005X40N#2 49.5,24.4 r90 bottom
R260 "100K" RESC1005X40N#2 47.8,24.4 r90 bottom
S2 "TDA02H0SB1" SW_TDA02 35.5,22.9 r180 top
SW1 "KSC221JLFS" SW_KSC221J 16.2,22.2 r270 top locked
SW2 "KSC221JLFS" SW_KSC221J 25.25,22.25 r270 top locked
TP1 "TESTPOINT" TP0762 61.13,22.72 r90 bottom
TP2 "TESTPOINT" TP0762 62.4,22.72 r90 bottom
TP3 "TESTPOINT" TP0762 56.45,50.15 r90 bottom
TP4 "TESTPOINT" TP0762 54.78,45.58 r90 bottom
TP5 "TESTPOINT" TP0762 54.775,44.175 r90 bottom
TP6 "TESTPOINT" TP0762 48.85,50.275 r90 bottom
TP7 "TESTPOINT" TP0762 49.1,47.625 r90 bottom
TP8 "TESTPOINT" TP0762 86.575,59.048 r90 bottom
TP9 "TESTPOINT" TP0762 83.2,51.7 r90 bottom
TP10 "TESTPOINT" TP0762 54.78,36.69 r90 bottom
TP13 "TESTPOINT" TP0762 41.7,21.9 r90 top
TP14 "TESTPOINT" TP0762 36.7,25.7 r90 top
TP15 "TESTPOINT" TP0762 23.61,58.45 r90 bottom
TP16 "TESTPOINT" TP0762 25.325,58.6 r90 bottom
TP18 "TESTPOINT" TP0762 82.72,41.77 r90 bottom
TP19 "TESTPOINT" TP0762 82.72,43.04 r90 bottom
TP20 "TESTPOINT" TP0762 82.72,44.31 r90 bottom
TP21 "TESTPOINT" TP0762 82.72,45.58 r90 bottom
U1 "CCWi-i.MX8X" CC8X_LGA 68.75,40.5 r270 top locked
U2 "SIP32401A" SON50P120X160X60-5T55X91N 36.125,61.29 r270 bottom
U3 "MP2316" QFN_MPS_MP2316 49.7,62.9 r180 bottom
U4 "NLASB3157DFT2G" SOT65P210X110-6N 23.55,44.475 r0 bottom
U5 "NLASB3157DFT2G" SOT65P210X110-6N 23.675,48.4 r0 bottom
U6 "TCAN1042HGVDR" SOIC127P600X175-8N 21,30.3 r180 top
U7 "TCAN1042HGVDR" SOIC127P600X175-8N 16.859,44.281 r180 bottom
U8 "LTC2862IS8-2#PBF" SOIC127P600X175-8N 16.9,50 r180 bottom locked
U9 "DMG1026UV-7" SOTFL50P160X60-6N 22.3,39 r180 bottom
U10 "SN74AVC2T245" QFN40P180X140X55-10N 14.625,32.15 r90 bottom
U11 "AR8031" QFN40P600X600X80-49T380N 25.54,30.192 r180 bottom
U12 "AR8031" QFN40P600X600X80-49T380N 29.1,42.8 r90 top locked
U13 "USB2514BI-AEZG" QFN50P600X600X100-37AN 29,56.5 r90 top locked
U14 "MIC2026" SOIC127P600X175-8N 55.3,24.5 r270 bottom
U15 "TPD4E001DRSR" SON95P300X300X80-7N 56.3,17.825 r270 top
U16 "TPD4E001DRSR" SON95P300X300X80-7N 15.175,22.1 r270 bottom
U17 "CBTU02043" PQFN40P160X240X55-17T140X60N 71.125,13.325 r90 bottom
U18 "PTN5110" QFN40P260X260X40-17T100X110N 73.3,17.3 r180 top
U19 "NX5P3290" BGA16N50P4X4_205X205X59B32N 71.13,18.3 r180 bottom
U20 "MAX98089" QFN40P700X700X80-57T560X560N 38.6,47.6 r180 bottom locked
U21 "SI2323DS-T1-E3" SOT95P240X110_GSD-3N 38.375,58.05 r90 bottom
U22 "DMG1026UV-7" SOTFL50P160X60-6N 21.025,59.775 r90 top
U23 "SI2323DS-T1-E3" SOT95P240X110_GSD-3N 29.45,23.325 r270 bottom
U24 "SI2323DS-T1-E3" SOT95P240X110_GSD-3N 38.2,57.775 r180 top
U25 "SI2323DS-T1-E3" SOT95P240X110_GSD-3N 36,38.4 r90 bottom
U26 "FDMA908PZ" FAIRCHILD_MICROFET_2X2 79.65,18.1 r270 bottom
U27 "AP2202" SOT95P280X145-5N 42.8,36.2 r270 bottom
U28 "AB-557-03-HCHC-F-L-C" QFN50P320X250X90-15T140X210N 97.525,46.725 r180 top
U29 "NTS0102GT" PSON50P195X100X50-8N 27.2,41.075 r270 bottom
U31 "MIC2026" SOIC127P600X175-8N 49.4,37 r270 bottom
U32 "SIP32401A" SON50P120X160X60-5T55X91N 28,64.35 r180 bottom
U33 "SIP32401A" SON50P120X160X60-5T55X91N 23.325,64.35 r180 bottom
X1 "RH100-25.000-20-EXT-TR" OSC210P320X250X90-4N 34.3,30.25 r180 bottom
X2 "RH100-25.000-20-EXT-TR" OSC210P320X250X90-4N 29.1,33.8 r90 top
X3 "24MHz" XTAL_C3E-3427 21.819,56.191 r90 top

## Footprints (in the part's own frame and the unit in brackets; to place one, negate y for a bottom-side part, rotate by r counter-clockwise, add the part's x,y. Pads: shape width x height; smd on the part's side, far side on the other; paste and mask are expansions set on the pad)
BGA16N50P4X4_205X205X59B32N [mm] "Ball Grid Array (BGA), 0.50 mm pitch, square; 16 pin, 2.05 mm L X 2.05 mm W X 0.595 mm H body"
  round 0.3 smd mask+0.05: A1(-0.75,0.75) A2(-0.25,0.75) A3(0.25,0.75) A4(0.75,0.75) B1(-0.75,0.25) B2(-0.25,0.25) B3(0.25,0.25) B4(0.75,0.25) C1(-0.75,-0.25) C2(-0.25,-0.25) C3(0.25,-0.25) C4(0.75,-0.25) D1(-0.75,-0.75) D2(-0.25,-0.75) D3(0.25,-0.75) D4(0.75,-0.75)
  body extent -1.02,-1.03 1.03,1.02, height 0.6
